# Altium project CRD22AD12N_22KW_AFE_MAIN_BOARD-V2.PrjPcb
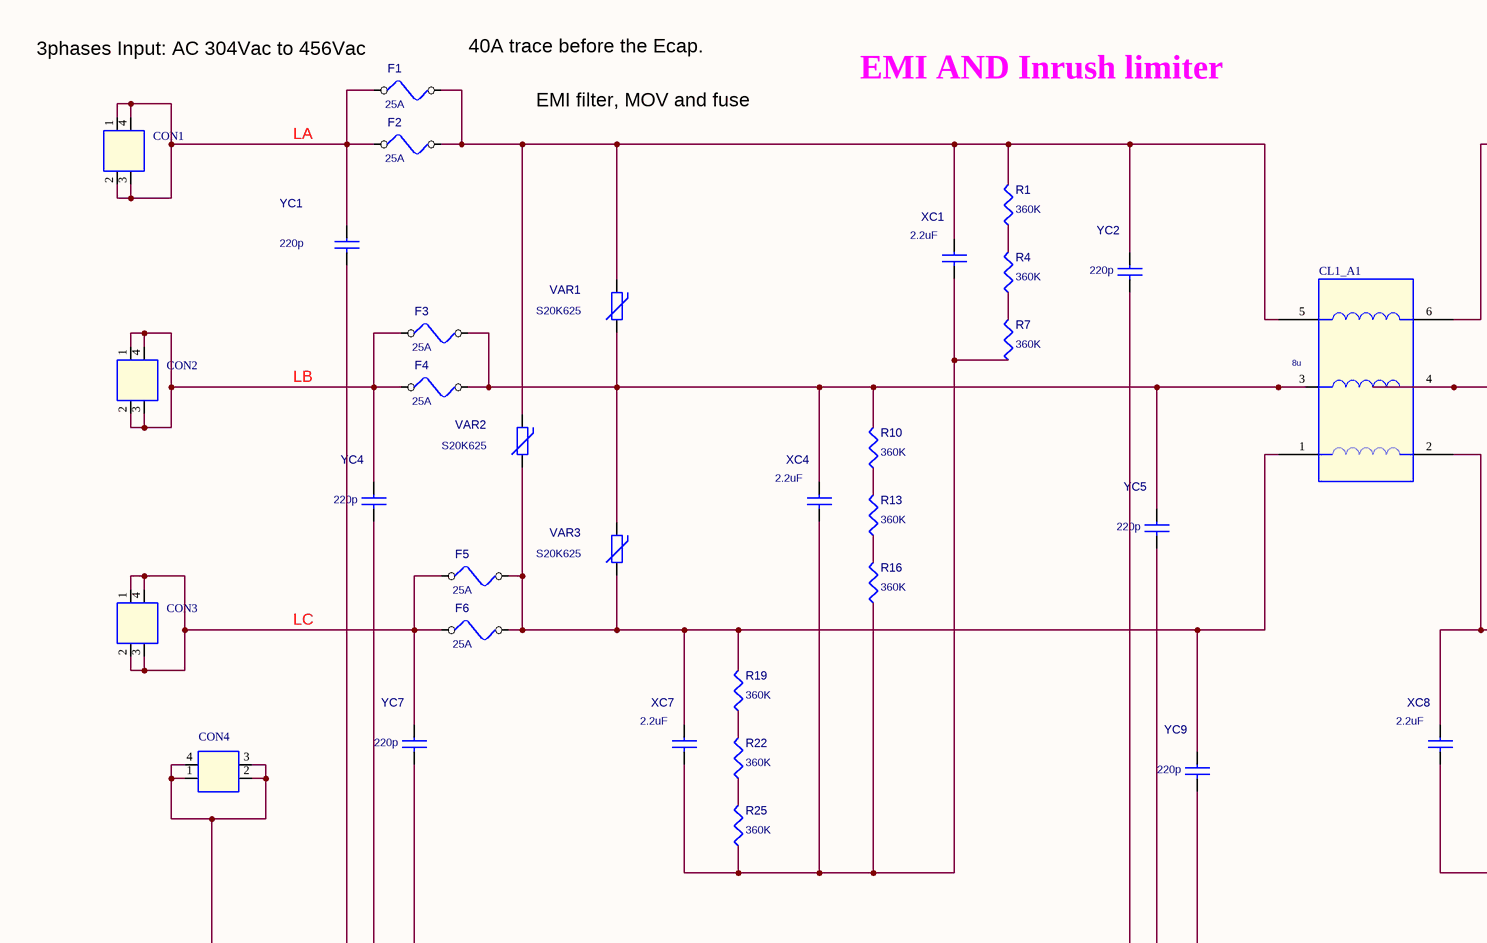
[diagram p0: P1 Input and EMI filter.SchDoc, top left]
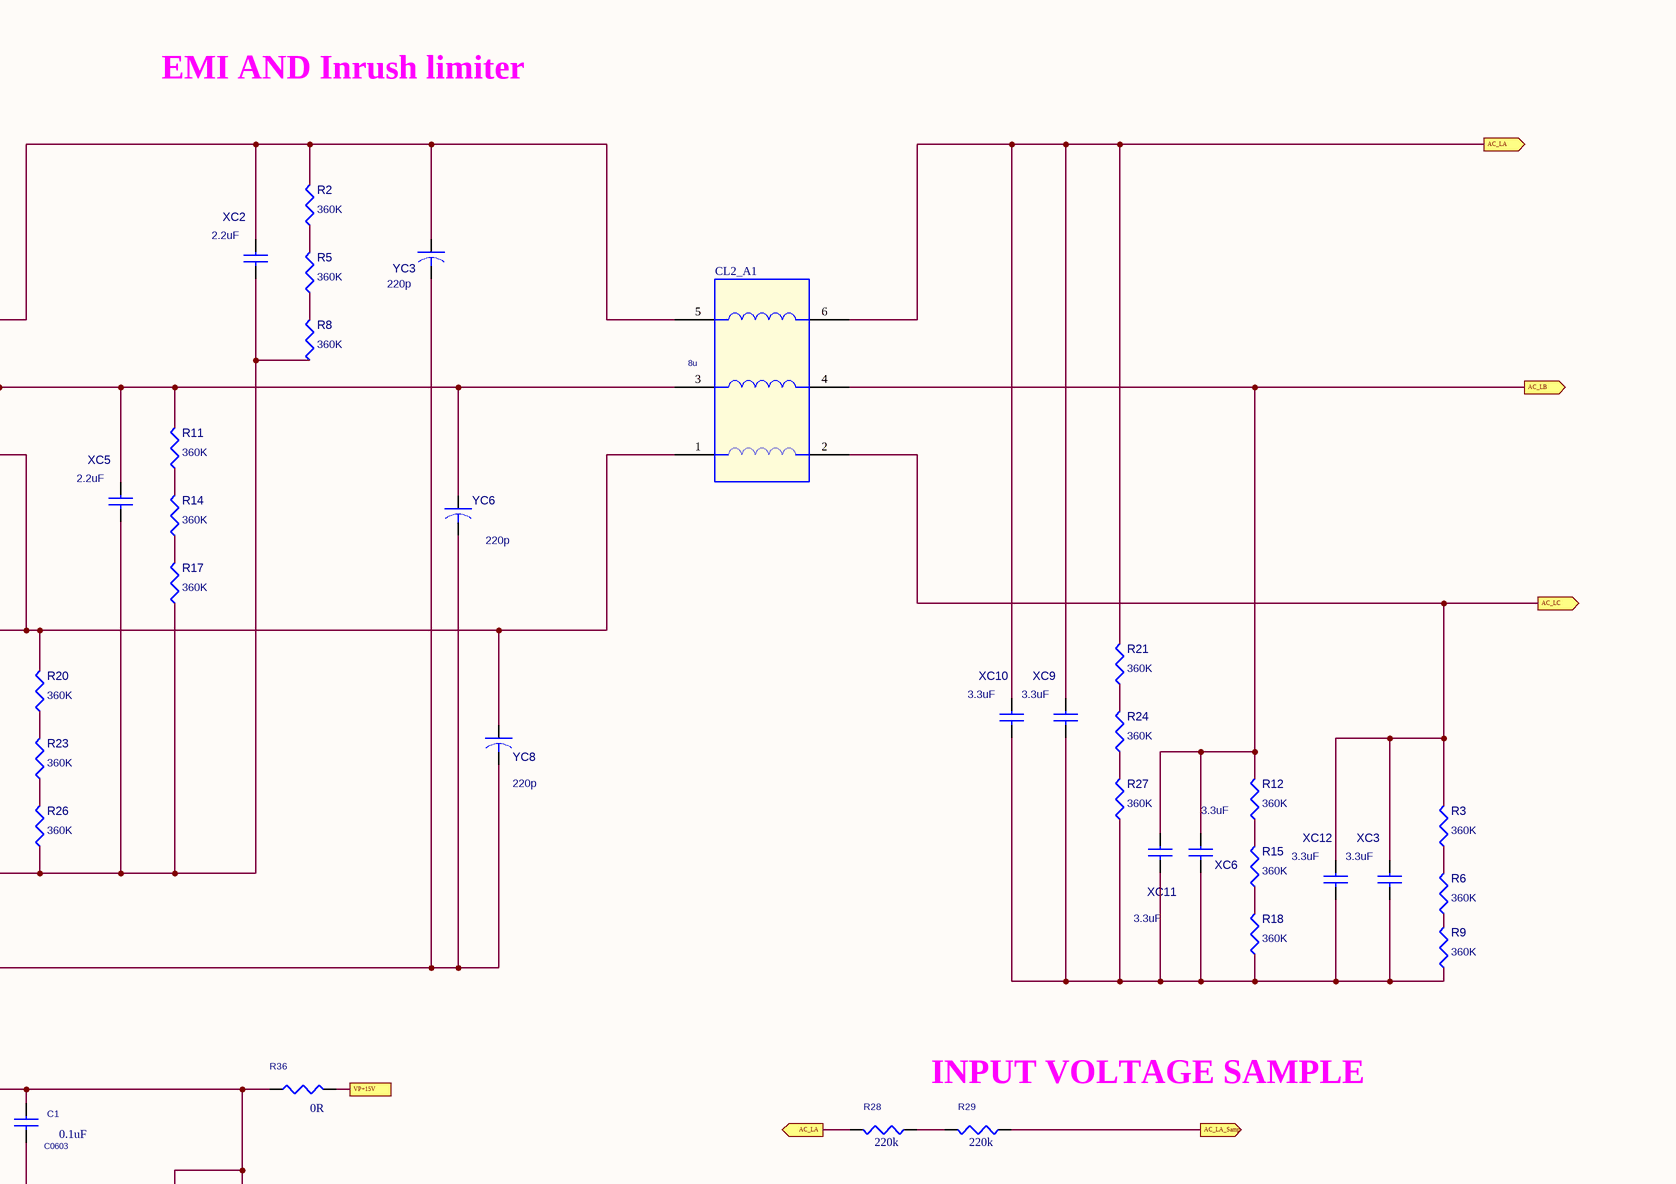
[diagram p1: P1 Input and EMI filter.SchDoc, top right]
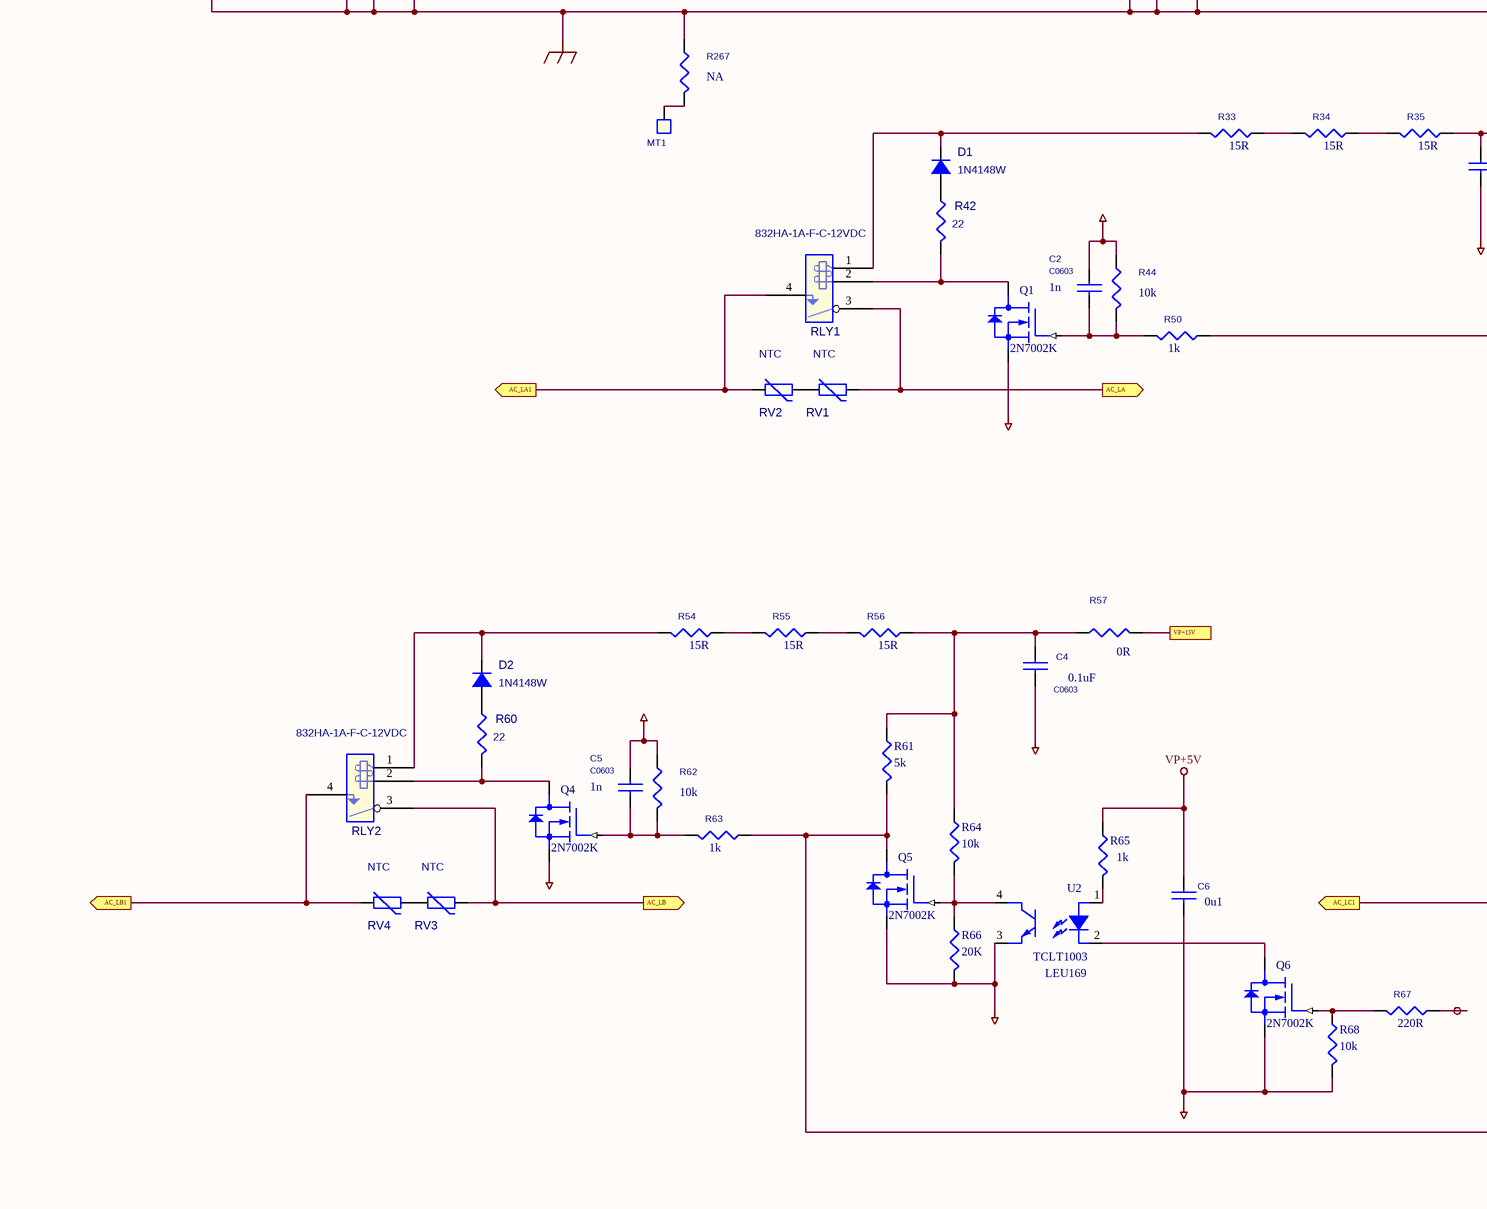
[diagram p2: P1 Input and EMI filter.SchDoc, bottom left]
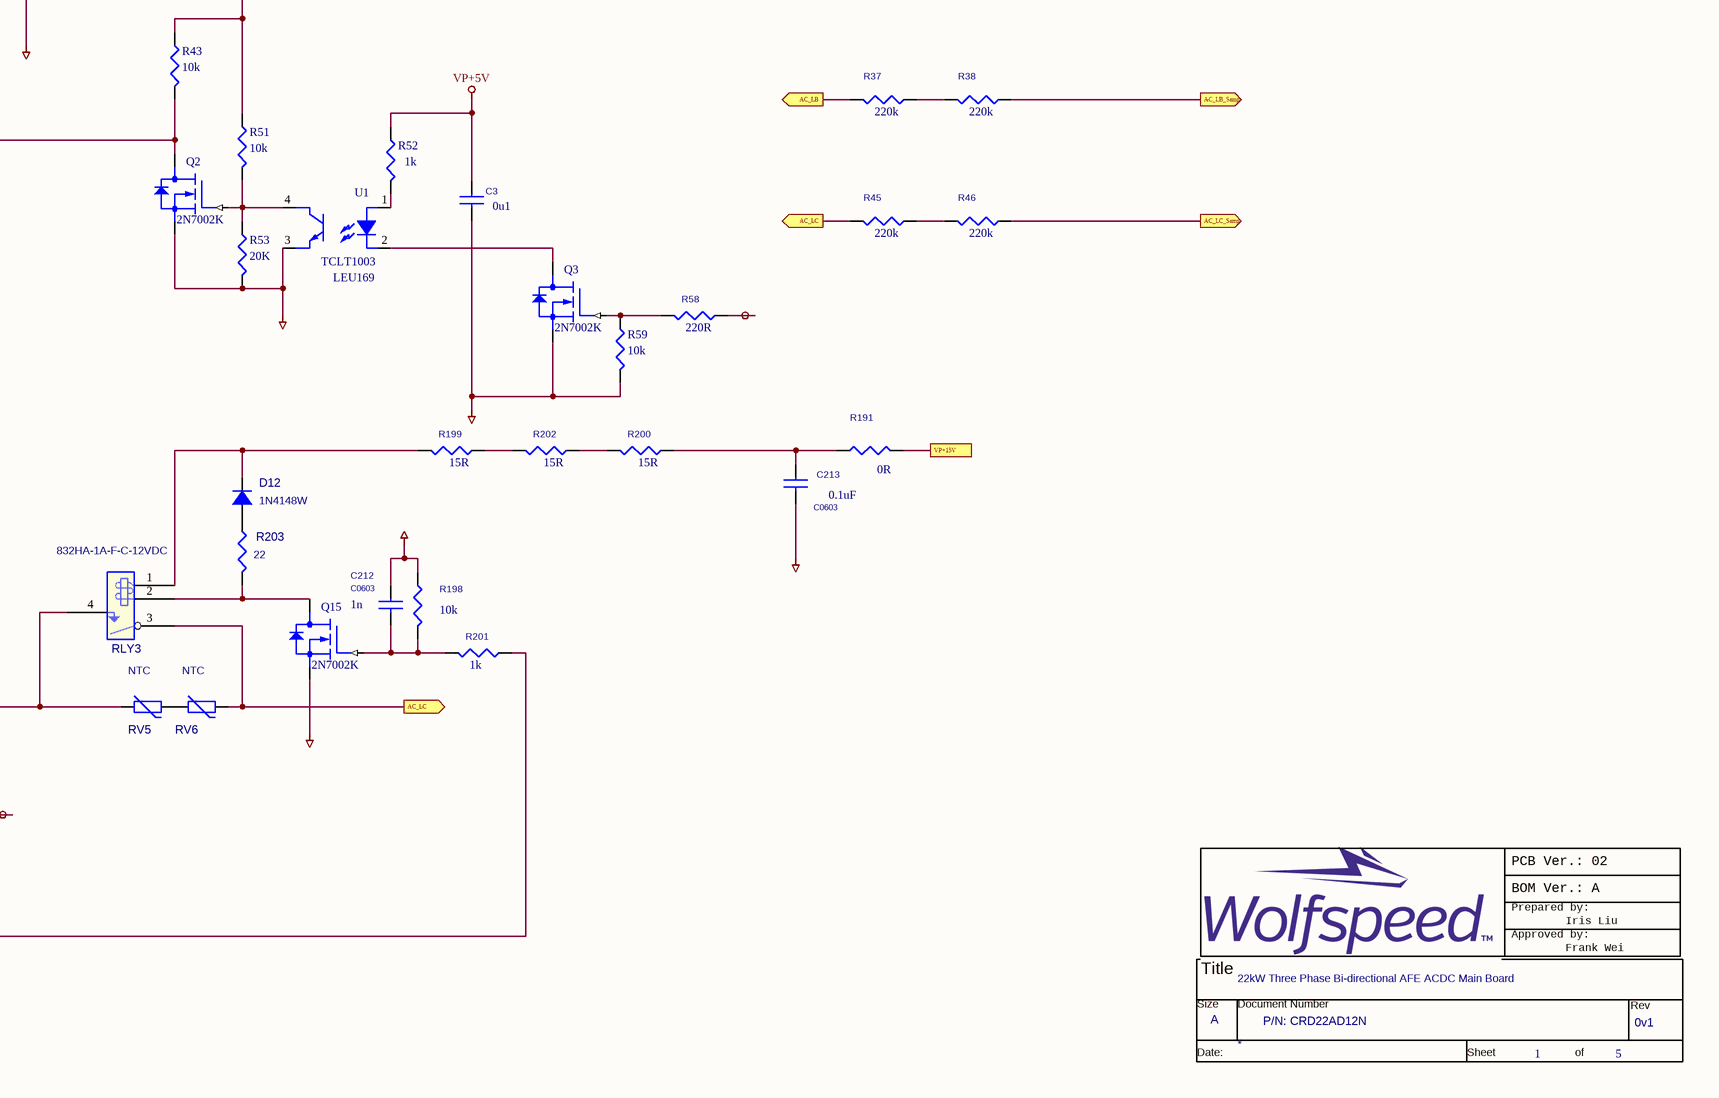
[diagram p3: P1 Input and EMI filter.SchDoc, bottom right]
5 sheets, 580 parts. Net scope: flat (ports and power ports of the same name join across sheets).
Board file: CRD22AD12N_22KW_AFE_MAIN_BOARD-V2.PcbDoc
Sheets:
  P1 Input and EMI filter.SchDoc
  P2 PFC.SchDoc
  P3 Bias POWER SUPPLY.SchDoc
  P4 PFC Gate Driver.SchDoc
  P5 PFC sampling.SchDoc

## Sheet P1 Input and EMI filter.SchDoc
size 594 x 420 mm

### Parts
(Parts that share a designator on the sheet are numbered #1, #2 ... from top to bottom, then left to right.)
*#1  Doc: P/N: CRD22AD12N  RevCode: 0v1  Title: 22kW Three Phase Bi-directional AFE ACDC Main Board  Page Size: A  Page Number: 1  Page Count: 5  (hidden comment: TitleBlock0_cree_power)  (graphical)
C1  0.1uF  [C0603]
C2  1n  [C0603]
C3  0u1  [C0603]
C4  0.1uF  [C0603]
C5  1n  [C0603]
C6  0u1  [C0603]
C212  1n  [C0603]
C213  0.1uF  [C0603]
CL1_A1  8u  [LCM1]
CL2_A1  8u  [LCM1]
CON1  Connecter  [thread4_9p9x5_1110x920]  (value not drawn)
CON2  Connecter  [thread4_9p9x5_1110x920]  (value not drawn)
CON3  Connecter  [thread4_9p9x5_1110x920]  (value not drawn)
CON4  Connecter  [thread4_9p9x5_1110x920]  (value not drawn)
D1  1N4148W  [SOD-123]
D2  1N4148W  [SOD-123]
D12  1N4148W  [SOD-123]
F1  25A  [FULSE]
F2  25A  [FULSE]
F3  25A  [FULSE]
F4  25A  [FULSE]
F5  25A  [FULSE]
F6  25A  [FULSE]
MT1  T1T2  [MTH122]  (value not drawn)
Q1  2N7002K  [SOT-23]
Q2  2N7002K  [SOT-23]
Q3  2N7002K  [SOT-23]
Q4  2N7002K  [SOT-23]
Q5  2N7002K  [SOT-23]
Q6  2N7002K  [SOT-23]
Q15  2N7002K  [SOT-23]
R1  360K  [R1206]
R2  360K  [R1206]
R3  360K  [R1206]
R4  360K  [R1206]
R5  360K  [R1206]
R6  360K  [R1206]
R7  360K  [R1206]
R8  360K  [R1206]
R9  360K  [R1206]
R10  360K  [R1206]
R11  360K  [R1206]
R12  360K  [R1206]
R13  360K  [R1206]
R14  360K  [R1206]
R15  360K  [R1206]
R16  360K  [R1206]
R17  360K  [R1206]
R18  360K  [R1206]
R19  360K  [R1206]
R20  360K  [R1206]
R21  360K  [R1206]
R22  360K  [R1206]
R23  360K  [R1206]
R24  360K  [R1206]
R25  360K  [R1206]
R26  360K  [R1206]
R27  360K  [R1206]
R28  220k  [R1206]
R29  220k  [R1206]
R33  15R  [R1206]
R34  15R  [R1206]
R35  15R  [R1206]
R36  0R  [R0603]
R37  220k  [R1206]
R38  220k  [R1206]
R42  22  [R1206]
R43  10k  [R0603]
R44  10k  [R0603]
R45  220k  [R1206]
R46  220k  [R1206]
R50  1k  [R0603]
R51  10k  [R0603]
R52  1k  [R0603]
R53  20K  [R0603]
R54  15R  [R1206]
R55  15R  [R1206]
R56  15R  [R1206]
R57  0R  [R0603]
R58  220R  [R0603]
R59  10k  [R0603]
R60  22  [R1206]
R61  5k  [R0603]
R62  10k  [R0603]
R63  1k  [R0603]
R64  10k  [R0603]
R65  1k  [R0603]
R66  20K  [R0603]
R67  220R  [R0603]
R68  10k  [R0603]
R191  0R  [R0603]
R198  10k  [R0603]
R199  15R  [R1206]
R200  15R  [R1206]
R201  1k  [R0603]
R202  15R  [R1206]
R203  22  [R1206]
R267  NA  [R1206]
RLY1  832HA-1A-F-C-12VDC  [T9SV1K15-12]
RLY2  832HA-1A-F-C-12VDC  [T9SV1K15-12]
RLY3  832HA-1A-F-C-12VDC  [T9SV1K15-12]
RV1  NTC  [NTC_od20MM]
RV2  NTC  [NTC_od20MM]
RV3  NTC  [NTC_od20MM]
RV4  NTC  [NTC_od20MM]
RV5  NTC  [NTC_od20MM]
RV6  NTC  [NTC_od20MM]
U1  TCLT1003  LLF Part Number: LEU169  [opto-sop-4l]
U2  TCLT1003  LLF Part Number: LEU169  [opto-sop-4l]
VAR1  S20K625  [MOV_OD21P5MM_PI10MM_PINV3P3MM]
VAR2  S20K625  [MOV_OD21P5MM_PI10MM_PINV3P3MM]
VAR3  S20K625  [MOV_OD21P5MM_PI10MM_PINV3P3MM]
XC1  2.2uF  [CAPFILM_26_5X12MM]
XC2  2.2uF  [CAPFILM_26_5X12MM]
XC3  3.3uF  [CAPFILM_26_5X15MM]
XC4  2.2uF  [CAPFILM_26_5X12MM]
XC5  2.2uF  [CAPFILM_26_5X12MM]
XC6  3.3uF  [CAPFILM_26_5X15MM]
XC7  2.2uF  [CAPFILM_26_5X12MM]
XC8  2.2uF  [CAPFILM_26_5X12MM]
XC9  3.3uF  [CAPFILM_26_5X15MM]
XC10  3.3uF  [CAPFILM_26_5X15MM]
XC11  3.3uF  [CAPFILM_26_5X15MM]
XC12  3.3uF  [CAPFILM_26_5X15MM]
YC1  220p  [C1812]
YC2  220p  [C1812]
YC3  220p  [C1812]
YC4  220p  [C1812]
YC5  220p  [C1812]
YC6  220p  [C1812]
YC7  220p  [C1812]
YC8  220p  [C1812]
YC9  220p  [C1812]

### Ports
AC_LA1 (out), AC_LA (out), AC_LA_Samp (out), AC_LB1 (out), AC_LB (out), AC_LB_Samp (out), AC_LC1 (out), AC_LC (out), AC_LC_Samp (out), VP+15V

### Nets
AGND: C3.2 C6.2 Q3.2(SOURCE) Q6.2(SOURCE) R59.1 R68.1
GGND: C1.2 C2.1 C4.2 C5.1 C212.1 C213.2 Q1.2(SOURCE) Q2.2(SOURCE) Q4.2(SOURCE) Q5.2(SOURCE) Q15.2(SOURCE) R44.2 R53.1 R62.2 R66.1 R198.2 U1.3 U2.3
GND_EARTH: CON4.1 CON4.2 CON4.3 CON4.4 R267.1 YC1.2 YC2.2 YC3.2 YC4.2 YC5.2 YC6.2 YC7.2 YC8.2 YC9.2
RLYCTRL1: R58.2
RLYCTRL2: R67.2
VP+5V: C3.1 C6.1 R52.2 R65.2
LA: CON1.1 CON1.2 CON1.3 CON1.4 F1.1 F2.1 YC1.1
LB: CON2.1 CON2.2 CON2.3 CON2.4 F3.1 F4.1 YC4.1
LC: CON3.1 CON3.2 CON3.3 CON3.4 F5.1 F6.1 YC7.1
NetC1_1: C1.1 R35.2 R36.2 R43.2 R51.2
NetC2_2: C2.2 Q1.1(GATE) R44.1 R50.1
NetC4_1: C4.1 R56.2 R57.2 R61.2 R64.2
NetC5_2: C5.2 Q4.1(GATE) R62.1 R63.1
NetC212_2: C212.2 Q15.1(GATE) R198.1 R201.1
NetC213_1: C213.1 R191.2 R200.2
NetCL1_A1_1: CL1_A1.1 F5.2 F6.2 R19.2 VAR2.1 VAR3.1 XC7.1 YC9.1
NetCL1_A1_2: CL1_A1.2 CL2_A1.1 R20.2 XC8.1 YC8.1
NetCL1_A1_3: CL1_A1.3 F3.2 F4.2 R10.2 VAR1.1 VAR3.2 XC4.1 YC5.1
NetCL1_A1_4: CL1_A1.4 CL2_A1.3 R11.2 XC5.1 YC6.1
NetCL1_A1_5: CL1_A1.5 F1.2 F2.2 R1.2 VAR1.2 VAR2.2 XC1.1 YC2.1
NetCL1_A1_6: CL1_A1.6 CL2_A1.5 R2.2 XC2.1 YC3.1
NetCL2_A1_2: CL2_A1.2 R3.2 R45.1 RLY3.3(COMMON) RV6.2 XC3.1 XC12.1 ; port AC_LC
NetCL2_A1_4: CL2_A1.4 R12.2 R37.1 RLY2.3(COMMON) RV3.2 XC6.1 XC11.1 ; port AC_LB
NetCL2_A1_6: CL2_A1.6 R21.2 R28.1 RLY1.3(COMMON) RV1.2 XC9.1 XC10.1 ; port AC_LA
NetD1_1: D1.1(A) R42.1
NetD1_2: D1.2(K) R33.1 RLY1.1(COIL2)
NetD2_1: D2.1(A) R60.1
NetD2_2: D2.2(K) R54.1 RLY2.1(COIL2)
NetD12_1: D12.1(A) R203.1
NetD12_2: D12.2(K) R199.1 RLY3.1(COIL2)
NetJ4_5: R36.1 R57.1 R191.1 ; port VP+15V
NetMT1_1: MT1.1 R267.2
NetQ1_3: Q1.3(DRAIN) R42.2 RLY1.2(COIL1)
NetQ2_1: Q2.1(GATE) R51.1 R53.2 U1.4
NetQ2_3: Q2.3(DRAIN) R43.1 R50.2
NetQ3_1: Q3.1(GATE) R58.1 R59.2
NetQ3_3: Q3.3(DRAIN) U1.2
NetQ4_3: Q4.3(DRAIN) R60.2 RLY2.2(COIL1)
NetQ5_1: Q5.1(GATE) R64.1 R66.2 U2.4
NetQ5_3: Q5.3(DRAIN) R61.1 R63.2 R201.2
NetQ6_1: Q6.1(GATE) R67.1 R68.2
NetQ6_3: Q6.3(DRAIN) U2.2
NetQ15_3: Q15.3(DRAIN) R203.2 RLY3.2(COIL1)
NetR1_1: R1.1 R4.2
NetR2_1: R2.1 R5.2
NetR3_1: R3.1 R6.2
NetR4_1: R4.1 R7.2
NetR5_1: R5.1 R8.2
NetR6_1: R6.1 R9.2
NetR7_1: R7.1 R16.1 R25.1 XC1.2 XC4.2 XC7.2
NetR8_1: R8.1 R17.1 R26.1 XC2.2 XC5.2 XC8.2
NetR9_1: R9.1 R18.1 R27.1 XC3.2 XC6.2 XC9.2 XC10.2 XC11.2 XC12.2
NetR10_1: R10.1 R13.2
NetR11_1: R11.1 R14.2
NetR12_1: R12.1 R15.2
NetR13_1: R13.1 R16.2
NetR14_1: R14.1 R17.2
NetR15_1: R15.1 R18.2
NetR19_1: R19.1 R22.2
NetR20_1: R20.1 R23.2
NetR21_1: R21.1 R24.2
NetR22_1: R22.1 R25.2
NetR23_1: R23.1 R26.2
NetR24_1: R24.1 R27.2
NetR28_2: R28.2 R29.1
NetR29_2: R29.2 ; port AC_LA_Samp
NetR33_2: R33.2 R34.1
NetR34_2: R34.2 R35.1
NetR37_2: R37.2 R38.1
NetR38_2: R38.2 ; port AC_LB_Samp
NetR45_2: R45.2 R46.1
NetR46_2: R46.2 ; port AC_LC_Samp
NetR52_1: R52.1 U1.1
NetR54_2: R54.2 R55.1
NetR55_2: R55.2 R56.1
NetR65_1: R65.1 U2.1
NetR199_2: R199.2 R202.1
NetR200_1: R200.1 R202.2
NetRLY1_4: RLY1.4(NO) RV2.1 ; port AC_LA1
NetRLY2_4: RLY2.4(NO) RV4.1 ; port AC_LB1
NetRLY3_4: RLY3.4(NO) RV5.1 ; port AC_LC1
NetRV1_1: RV1.1 RV2.2
NetRV3_1: RV3.1 RV4.2
NetRV5_2: RV5.2 RV6.1

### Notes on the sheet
- (near F1) 3phases Input: AC 304Vac to 456Vac
- (near F1) 40A trace before the Ecap.
- EMI AND Inrush limiter
- EMI filter, MOV and fuse
- INPUT VOLTAGE SAMPLE
- PCB Ver.: 02
- BOM Ver.: A
- Prepared by:
- Approved by:
- .
- Frank Wei
- Iris Liu

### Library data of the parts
C1-C6 C212 C213 XC1-XC12 YC1 YC2 YC4 YC5 YC7 YC9 = CAP NP
CL1_A1 CL2_A1 = 126LNS_5
D1 D2 D12 = DIODE_0
F1-F6 = FUSE_0
MT1 = CON1_2
Q1-Q6 Q15 = 2N7002/SOT
R1-R27 = R_2
R28 R29 R33-R38 R43-R46 R50-R59 R61-R68 R191 R198-R202 R267 = RESISTOR
R42 R60 R203 = RESISTOR_Dup1
RLY1-RLY3 = RELAY SPST_1
RV1-RV6 VAR1-VAR3 = VARISTOR
U1 U2 = LEU169_TCLT1003_SOP-4L
YC3 YC6 YC8 = CAP

## Sheet P2 PFC.SchDoc
size 594 x 420 mm
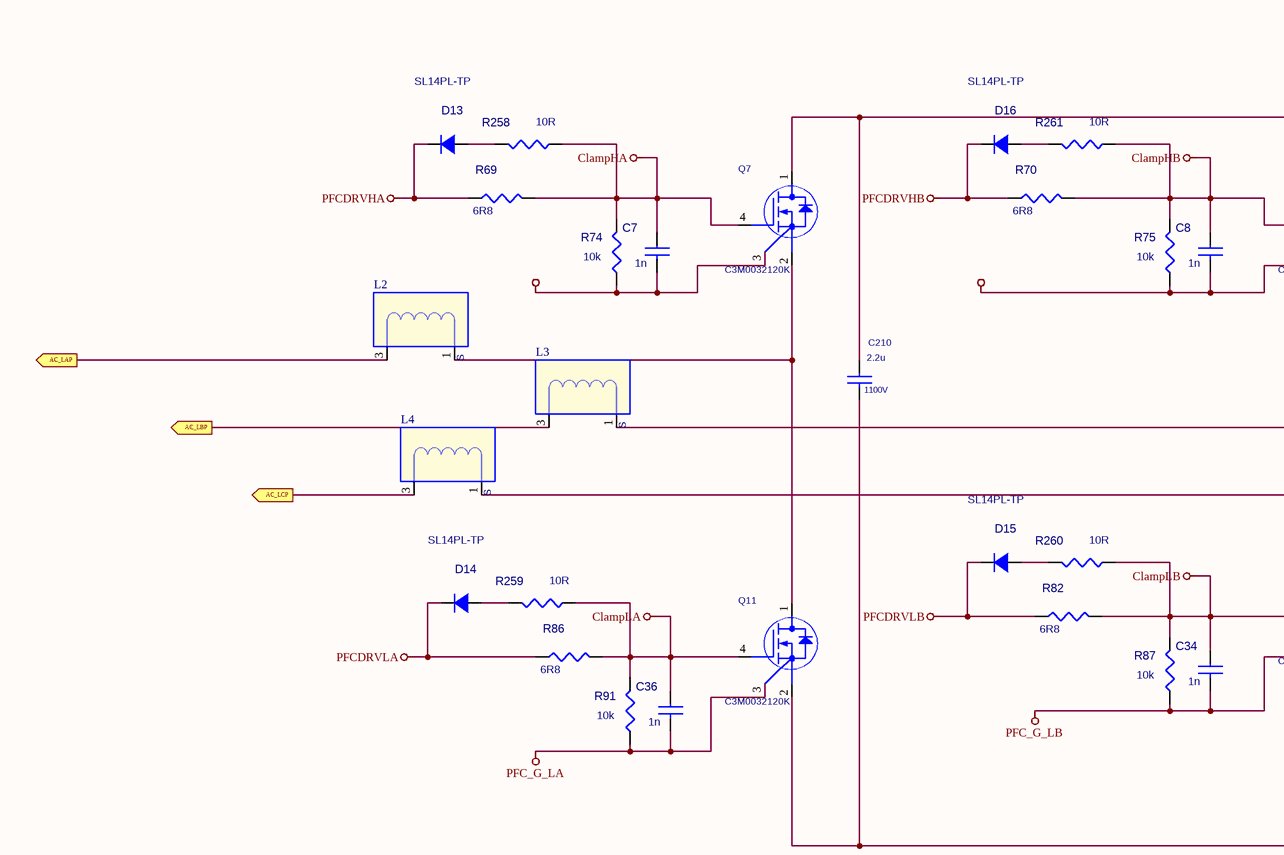
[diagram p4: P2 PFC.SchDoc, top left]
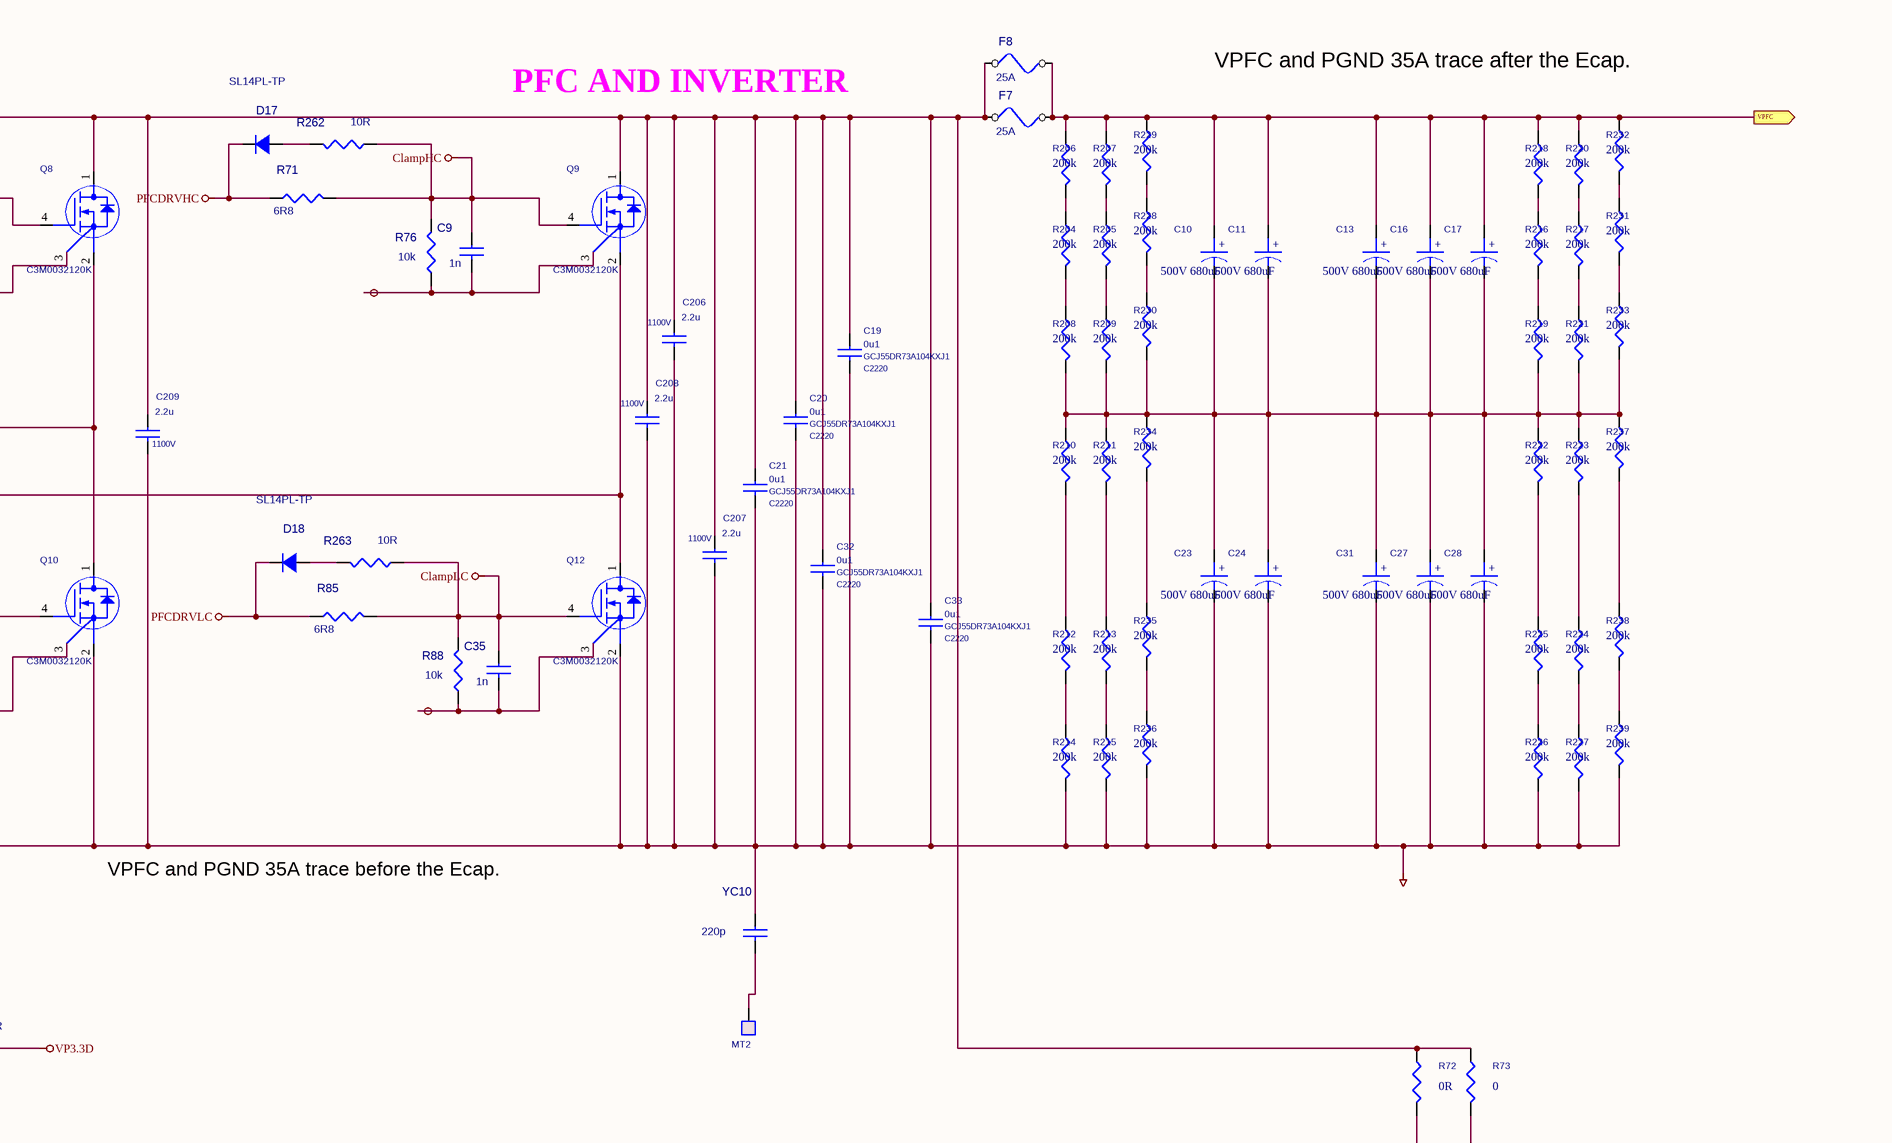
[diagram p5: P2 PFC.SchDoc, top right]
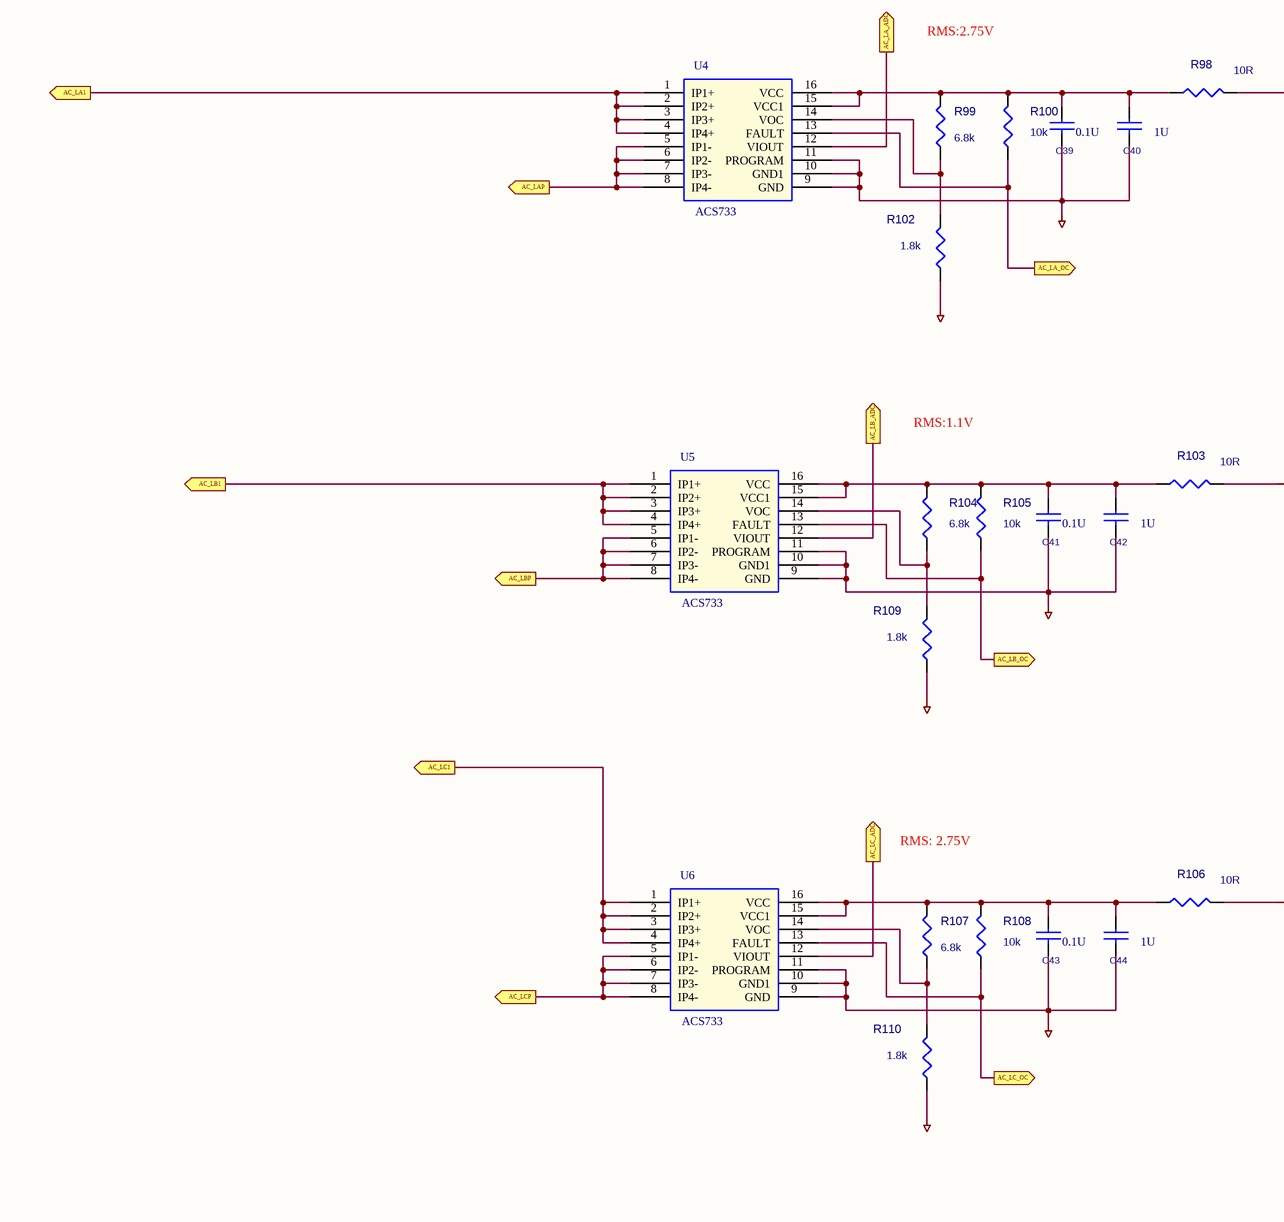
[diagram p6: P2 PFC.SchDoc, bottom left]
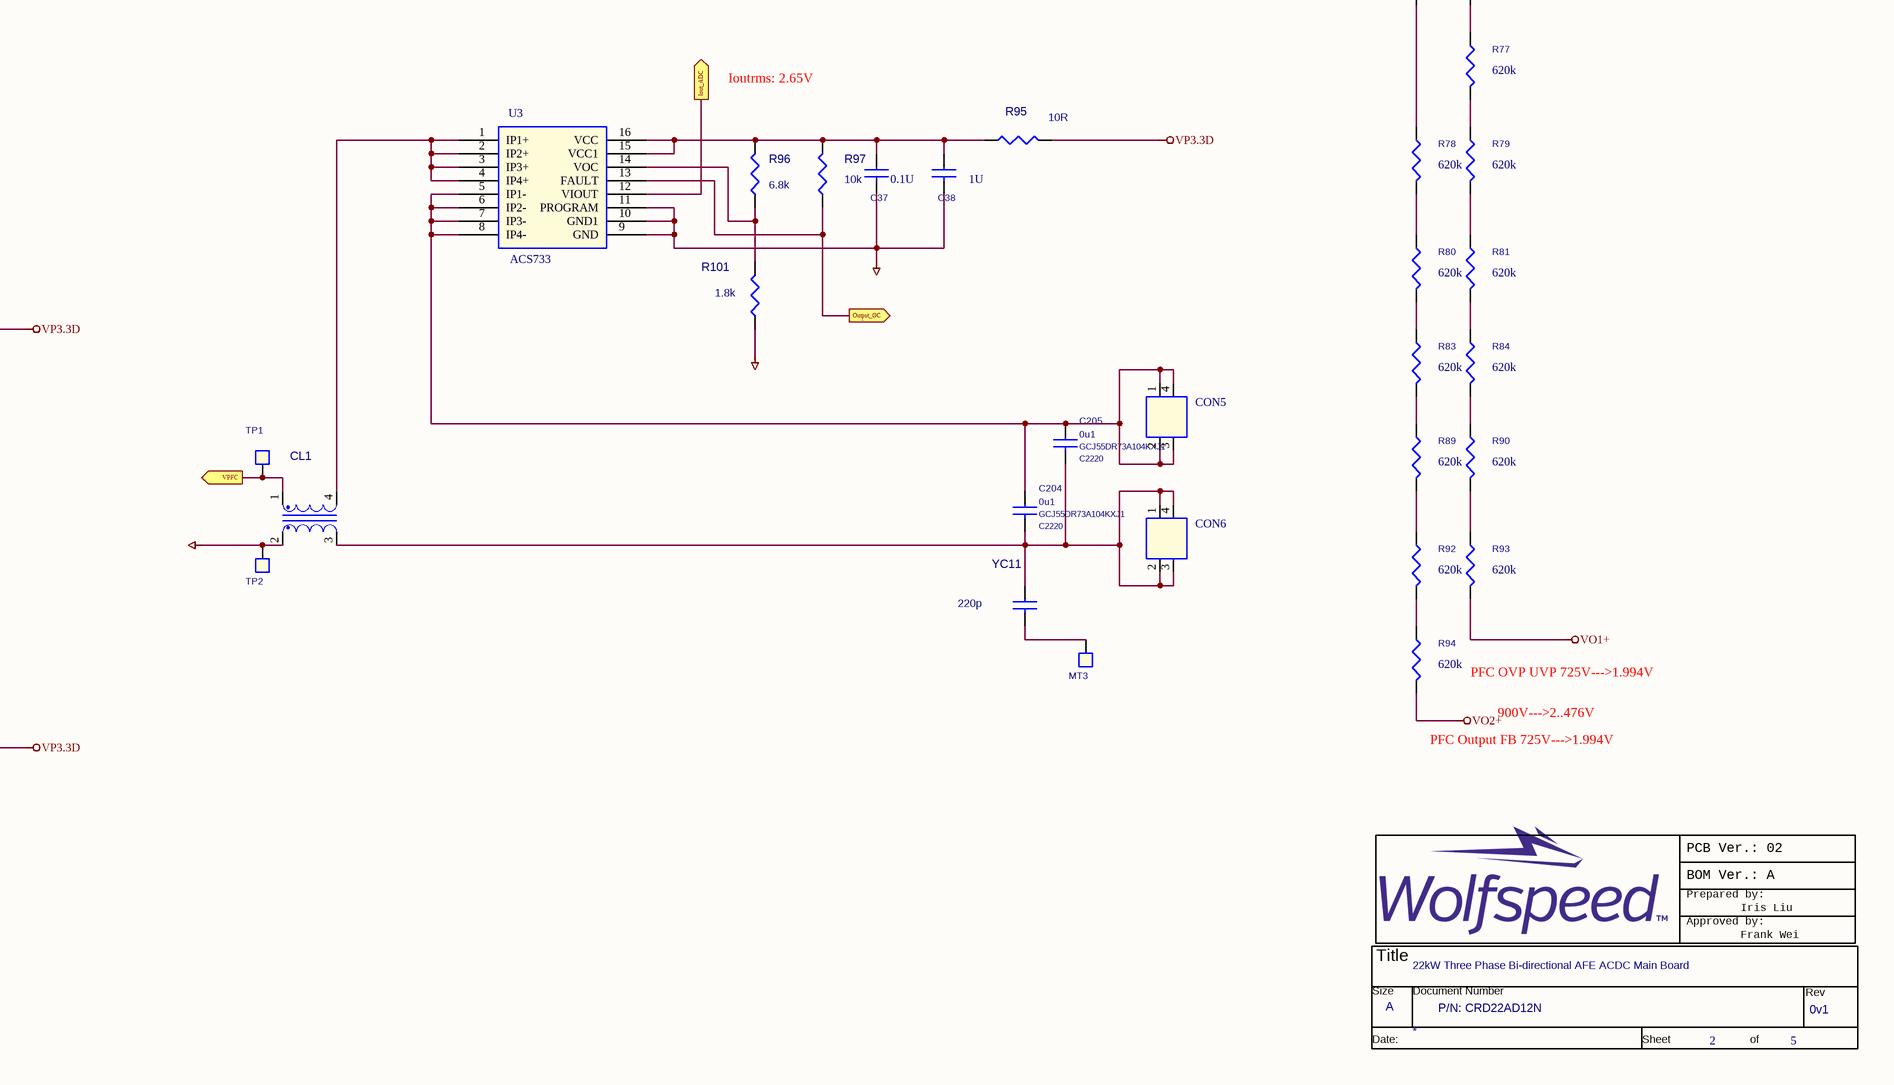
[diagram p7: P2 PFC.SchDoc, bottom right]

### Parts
(Parts that share a designator on the sheet are numbered #1, #2 ... from top to bottom, then left to right.)
*#2  Doc: P/N: CRD22AD12N  RevCode: 0v1  Title: 22kW Three Phase Bi-directional AFE ACDC Main Board  Page Size: A  Page Number: 2  Page Count: 5  (hidden comment: TitleBlock0_cree_power)  (graphical)
C7  1n  [C0603]
C8  1n  [C0603]
C9  1n  [C0603]
C10  500V 680uF  [ecap_d35p7_25]
C11  500V 680uF  [ecap_d35p7_25]
C13  500V 680uF  [ecap_d35p7_25]
C16  500V 680uF  [ecap_d35p7_25]
C17  500V 680uF  [ecap_d35p7_25]
C19  0u1  value1: GCJ55DR73A104KXJ1  [C2220]
C20  0u1  value1: GCJ55DR73A104KXJ1  [C2220]
C21  0u1  value1: GCJ55DR73A104KXJ1  [C2220]
C23  500V 680uF  [ecap_d35p7_25]
C24  500V 680uF  [ecap_d35p7_25]
C27  500V 680uF  [ecap_d35p7_25]
C28  500V 680uF  [ecap_d35p7_25]
C31  500V 680uF  [ecap_d35p7_25]
C32  0u1  value1: GCJ55DR73A104KXJ1  [C2220]
C33  0u1  value1: GCJ55DR73A104KXJ1  [C2220]
C34  1n  [C0603]
C35  1n  [C0603]
C36  1n  [C0603]
C37  0.1U  [C0603]
C38  1U  [C0603]
C39  0.1U  [C0603]
C40  1U  [C0603]
C41  0.1U  [C0603]
C42  1U  [C0603]
C43  0.1U  [C0603]
C44  1U  [C0603]
C204  0u1  value1: GCJ55DR73A104KXJ1  [C2220]
C205  0u1  value1: GCJ55DR73A104KXJ1  [C2220]
C206  2.2u  value1: 1100V  [capfilm_31_5x12_5mm]
C207  2.2u  value1: 1100V  [capfilm_31_5x12_5mm]
C208  2.2u  value1: 1100V  [capfilm_31_5x12_5mm]
C209  2.2u  value1: 1100V  [capfilm_31_5x12_5mm]
C210  2.2u  value1: 1100V  [capfilm_31_5x12_5mm]
CL1  6Ts  [CM_4P]  (value not drawn)
CON5  Connecter  [thread4_9p9x5_1110x920]  (value not drawn)
CON6  Connecter  [thread4_9p9x5_1110x920]  (value not drawn)
D13  SL14PL-TP  [SOD-123]
D14  SL14PL-TP  [SOD-123]
D15  SL14PL-TP  [SOD-123]
D16  SL14PL-TP  [SOD-123]
D17  SL14PL-TP  [SOD-123]
D18  SL14PL-TP  [SOD-123]
F7  25A  [FULSE]
F8  25A  [FULSE]
L2  8u  [L71mm]  (value not drawn)
L3  8u  [L71mm]  (value not drawn)
L4  8u  [L71mm]  (value not drawn)
MT2  T1T2  [MTH122]  (value not drawn)
MT3  T1T2  [MTH122]  (value not drawn)
Q7  C3M0032120K  [to-247-4l]
Q8  C3M0032120K  [to-247-4l]
Q9  C3M0032120K  [to-247-4l]
Q10  C3M0032120K  [to-247-4l]
Q11  C3M0032120K  [to-247-4l]
Q12  C3M0032120K  [to-247-4l]
R69  6R8  [R1206]
R70  6R8  [R1206]
R71  6R8  [R1206]
R72  0R  [R1206]
R73  0  [R1206]
R74  10k  [R0603]
R75  10k  [R0603]
R76  10k  [R0603]
R77  620k  [R1206]
R78  620k  [R1206]
R79  620k  [R1206]
R80  620k  [R1206]
R81  620k  [R1206]
R82  6R8  [R1206]
R83  620k  [R1206]
R84  620k  [R1206]
R85  6R8  [R1206]
R86  6R8  [R1206]
R87  10k  [R0603]
R88  10k  [R0603]
R89  620k  [R1206]
R90  620k  [R1206]
R91  10k  [R0603]
R92  620k  [R1206]
R93  620k  [R1206]
R94  620k  [R1206]
R95  10R  [R0603]
R96  6.8k  [R0603]
R97  10k  [R0603]
R98  10R  [R0603]
R99  6.8k  [R0603]
R100  10k  [R0603]
R101  1.8k  [R0603]
R102  1.8k  [R0603]
R103  10R  [R0603]
R104  6.8k  [R0603]
R105  10k  [R0603]
R106  10R  [R0603]
R107  6.8k  [R0603]
R108  10k  [R0603]
R109  1.8k  [R0603]
R110  1.8k  [R0603]
R204  200k  [R1206]
R205  200k  [R1206]
R206  200k  [R1206]
R207  200k  [R1206]
R208  200k  [R1206]
R209  200k  [R1206]
R210  200k  [R1206]
R211  200k  [R1206]
R212  200k  [R1206]
R213  200k  [R1206]
R214  200k  [R1206]
R215  200k  [R1206]
R216  200k  [R1206]
R217  200k  [R1206]
R218  200k  [R1206]
R219  200k  [R1206]
R220  200k  [R1206]
R221  200k  [R1206]
R222  200k  [R1206]
R223  200k  [R1206]
R224  200k  [R1206]
R225  200k  [R1206]
R226  200k  [R1206]
R227  200k  [R1206]
R228  200k  [R1206]
R229  200k  [R1206]
R230  200k  [R1206]
R231  200k  [R1206]
R232  200k  [R1206]
R233  200k  [R1206]
R234  200k  [R1206]
R235  200k  [R1206]
R236  200k  [R1206]
R237  200k  [R1206]
R238  200k  [R1206]
R239  200k  [R1206]
R258  10R  [R1206]
R259  10R  [R1206]
R260  10R  [R1206]
R261  10R  [R1206]
R262  10R  [R1206]
R263  10R  [R1206]
TP1  T1T2  [TH47_CR98]  (value not drawn)
TP2  T1T2  [TH47_CR98]  (value not drawn)
U3  ACS733  [SOICW-16]
U4  ACS733  [SOICW-16]
U5  ACS733  [SOICW-16]
U6  ACS733  [SOICW-16]
YC10  220p  [C1812]
YC11  220p  [C1812]

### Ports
AC_LA1 (out), AC_LA_ADC (out), AC_LA_OC (out), AC_LAP (out), AC_LB1 (out), AC_LB_ADC (out), AC_LB_OC (out), AC_LBP (out), AC_LC1 (out), AC_LC_ADC (out), AC_LC_OC (out), AC_LCP (out), Iout_ADC (out), Output_OC (out), VPFC (out)

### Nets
AGND: C37.2 C38.2 C39.2 C40.2 C41.2 C42.2 C43.2 C44.2 R101.2 R102.2 R109.2 R110.2 U3.9(GND) U3.10(GND1) U3.11(PROGRAM) U4.9(GND) U4.10(GND1) U4.11(PROGRAM) U5.9(GND) U5.10(GND1) U5.11(PROGRAM) U6.9(GND) U6.10(GND1) U6.11(PROGRAM)
ClampHA: C7.1 Q7.4(G) R69.2 R74.2 R258.1
ClampHB: C8.1 Q8.4(G) R70.2 R75.2 R261.1
ClampHC: C9.1 Q9.4(G) R71.2 R76.2 R262.1
ClampLA: C36.1 Q11.4(G) R86.2 R91.2 R259.1
ClampLB: C34.1 Q10.4(G) R82.2 R87.2 R260.1
ClampLC: C35.1 Q12.4(G) R85.2 R88.2 R263.1
PFC_G_HA: C7.2 Q7.3(GS) R74.1
PFC_G_HB: C8.2 Q8.3(GS) R75.1
PFC_G_HC: C9.2 Q9.3(GS) R76.1
PFC_G_LA: C36.2 Q11.3(GS) R91.1
PFC_G_LB: C34.2 Q10.3(GS) R87.1
PFC_G_LC: C35.2 Q12.3(GS) R88.1
PFCDRVHA: D13.2(K) R69.1
PFCDRVHB: D16.2(K) R70.1
PFCDRVHC: D17.2(K) R71.1
PFCDRVLA: D14.2(K) R86.1
PFCDRVLB: D15.2(K) R82.1
PFCDRVLC: D18.2(K) R85.1
PGND: C19.2 C20.2 C21.2 C23.2 C24.2 C27.2 C28.2 C31.2 C32.2 C33.2 C206.2 C207.2 C208.2 C209.2 C210.2 CL1.2(P21) Q10.2(S) Q11.2(S) Q12.2(S) R214.1 R215.1 R226.1 R227.1 R236.1 R239.1 TP2.1 YC10.1
VO1+: R93.1
VO2+: R94.1
VP3.3D: R95.1 R98.1 R103.1 R106.1
NetC10_1: C10.1 C11.1 C13.1 C16.1 C17.1 CL1.1(P11) F7.2 F8.2 R206.2 R207.2 R218.2 R220.2 R229.2 R232.2 TP1.1 ; port VPFC
NetC10_2: C10.2 C11.2 C13.2 C16.2 C17.2 C23.1 C24.1 C27.1 C28.1 C31.1 R208.1 R209.1 R210.2 R211.2 R219.1 R221.1 R222.2 R223.2 R230.1 R233.1 R234.2 R237.2
NetC19_1: C19.1 C20.1 C21.1 C32.1 C33.1 C206.1 C207.1 C208.1 C209.1 C210.1 F7.1 F8.1 Q7.1(D) Q8.1(D) Q9.1(D) R72.2 R73.2
NetC37_1: C37.1 C38.1 R95.2 R96.1 R97.1 U3.15(VCC1) U3.16(VCC)
NetC39_1: C39.1 C40.1 R98.2 R99.1 R100.1 U4.15(VCC1) U4.16(VCC)
NetC41_1: C41.1 C42.1 R103.2 R104.1 R105.1 U5.15(VCC1) U5.16(VCC)
NetC43_1: C43.1 C44.1 R106.2 R107.1 R108.1 U6.15(VCC1) U6.16(VCC)
NetC204_1: C204.1 C205.1 CON5.1 CON5.2 CON5.3 CON5.4 U3.5(IP1-) U3.6(IP2-) U3.7(IP3-) U3.8(IP4-)
NetC204_2: C204.2 C205.2 CL1.3(P22) CON6.1 CON6.2 CON6.3 CON6.4 YC11.1
NetCL1_4: CL1.4(P12) U3.1(IP1+) U3.2(IP2+) U3.3(IP3+) U3.4(IP4+)
NetD13_1: D13.1(A) R258.2
NetD14_1: D14.1(A) R259.2
NetD15_1: D15.1(A) R260.2
NetD16_1: D16.1(A) R261.2
NetD17_1: D17.1(A) R262.2
NetD18_1: D18.1(A) R263.2
NetJ1_8: R100.2 U4.13(FAULT) ; port AC_LA_OC
NetJ1_10: R105.2 U5.13(FAULT) ; port AC_LB_OC
NetJ1_12: R108.2 U6.13(FAULT) ; port AC_LC_OC
NetJ1_14: U3.12(VIOUT) ; port Iout_ADC
NetJ1_15: U4.12(VIOUT) ; port AC_LA_ADC
NetJ1_16: R97.2 U3.13(FAULT) ; port Output_OC
NetJ1_17: U5.12(VIOUT) ; port AC_LB_ADC
NetJ1_19: U6.12(VIOUT) ; port AC_LC_ADC
NetL2_1: L2.1 Q7.2(S) Q11.1(D)
NetL2_3: L2.3 U4.5(IP1-) U4.6(IP2-) U4.7(IP3-) U4.8(IP4-) ; port AC_LAP
NetL3_1: L3.1 Q8.2(S) Q10.1(D)
NetL3_3: L3.3 U5.5(IP1-) U5.6(IP2-) U5.7(IP3-) U5.8(IP4-) ; port AC_LBP
NetL4_1: L4.1 Q9.2(S) Q12.1(D)
NetL4_3: L4.3 U6.5(IP1-) U6.6(IP2-) U6.7(IP3-) U6.8(IP4-) ; port AC_LCP
NetMT2_1: MT2.1 YC10.2
NetMT3_1: MT3.1 YC11.2
NetR72_1: R72.1 R78.2
NetR73_1: R73.1 R77.2
NetR77_1: R77.1 R79.2
NetR78_1: R78.1 R80.2
NetR79_1: R79.1 R81.2
NetR80_1: R80.1 R83.2
NetR81_1: R81.1 R84.2
NetR83_1: R83.1 R89.2
NetR84_1: R84.1 R90.2
NetR89_1: R89.1 R92.2
NetR90_1: R90.1 R93.2
NetR92_1: R92.1 R94.2
NetR96_2: R96.2 R101.1 U3.14(VOC)
NetR99_2: R99.2 R102.1 U4.14(VOC)
NetR104_2: R104.2 R109.1 U5.14(VOC)
NetR107_2: R107.2 R110.1 U6.14(VOC)
NetR204_1: R204.1 R208.2
NetR204_2: R204.2 R206.1
NetR205_1: R205.1 R209.2
NetR205_2: R205.2 R207.1
NetR210_1: R210.1 R212.2
NetR211_1: R211.1 R213.2
NetR212_1: R212.1 R214.2
NetR213_1: R213.1 R215.2
NetR216_1: R216.1 R219.2
NetR216_2: R216.2 R218.1
NetR217_1: R217.1 R221.2
NetR217_2: R217.2 R220.1
NetR222_1: R222.1 R225.2
NetR223_1: R223.1 R224.2
NetR224_1: R224.1 R227.2
NetR225_1: R225.1 R226.2
NetR228_1: R228.1 R230.2
NetR228_2: R228.2 R229.1
NetR231_1: R231.1 R233.2
NetR231_2: R231.2 R232.1
NetR234_1: R234.1 R235.2
NetR235_1: R235.1 R236.2
NetR237_1: R237.1 R238.2
NetR238_1: R238.1 R239.2
NetRLY1_4: U4.1(IP1+) U4.2(IP2+) U4.3(IP3+) U4.4(IP4+) ; port AC_LA1
NetRLY2_4: U5.1(IP1+) U5.2(IP2+) U5.3(IP3+) U5.4(IP4+) ; port AC_LB1
NetRLY3_4: U6.1(IP1+) U6.2(IP2+) U6.3(IP3+) U6.4(IP4+) ; port AC_LC1

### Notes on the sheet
- PFC AND INVERTER
- VPFC and PGND 35A trace after the Ecap.
- VPFC and PGND 35A trace before the Ecap.
- RMS:2.75V
- Ioutrms: 2.65V
- RMS:1.1V
- PFC OVP UVP 725V--->1.994V
- RMS: 2.75V
- PFC Output FB 725V--->1.994V
- 900V--->2..476V
- PCB Ver.: 02
- BOM Ver.: A
- Prepared by:
- Approved by:
- .
- Frank Wei
- Iris Liu

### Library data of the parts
*#2 = TitleBlock0_cree_power: Schematic Page Count: 4; Schematic Page Number: 1
C7-C9 C19-C21 C32-C36 C204-C210 = CAP NP_Dup1
C10 C11 C13 C16 C17 C23 C24 C27 C28 C31 = CAP POL
C37-C44 YC10 YC11 = CAP NP
CL1 = TRNSFMR 67125450_0
D13-D18 = DIODE_0
F7 F8 = FUSE_0
L2-L4 = 126LNS_1
MT2 MT3 TP1 TP2 = CON1_2
Q7-Q12 = C3M0065090J_4
R69-R71 R74-R76 R82 R85-R88 R91 R95-R110 R258-R263 = R
R72 R73 R77-R81 R83 R84 R89 R90 R92-R94 R204-R239 = RESISTOR
U3-U6 = MCR1101_0

## Sheet P3 Bias POWER SUPPLY.SchDoc
size 840 x 594 mm
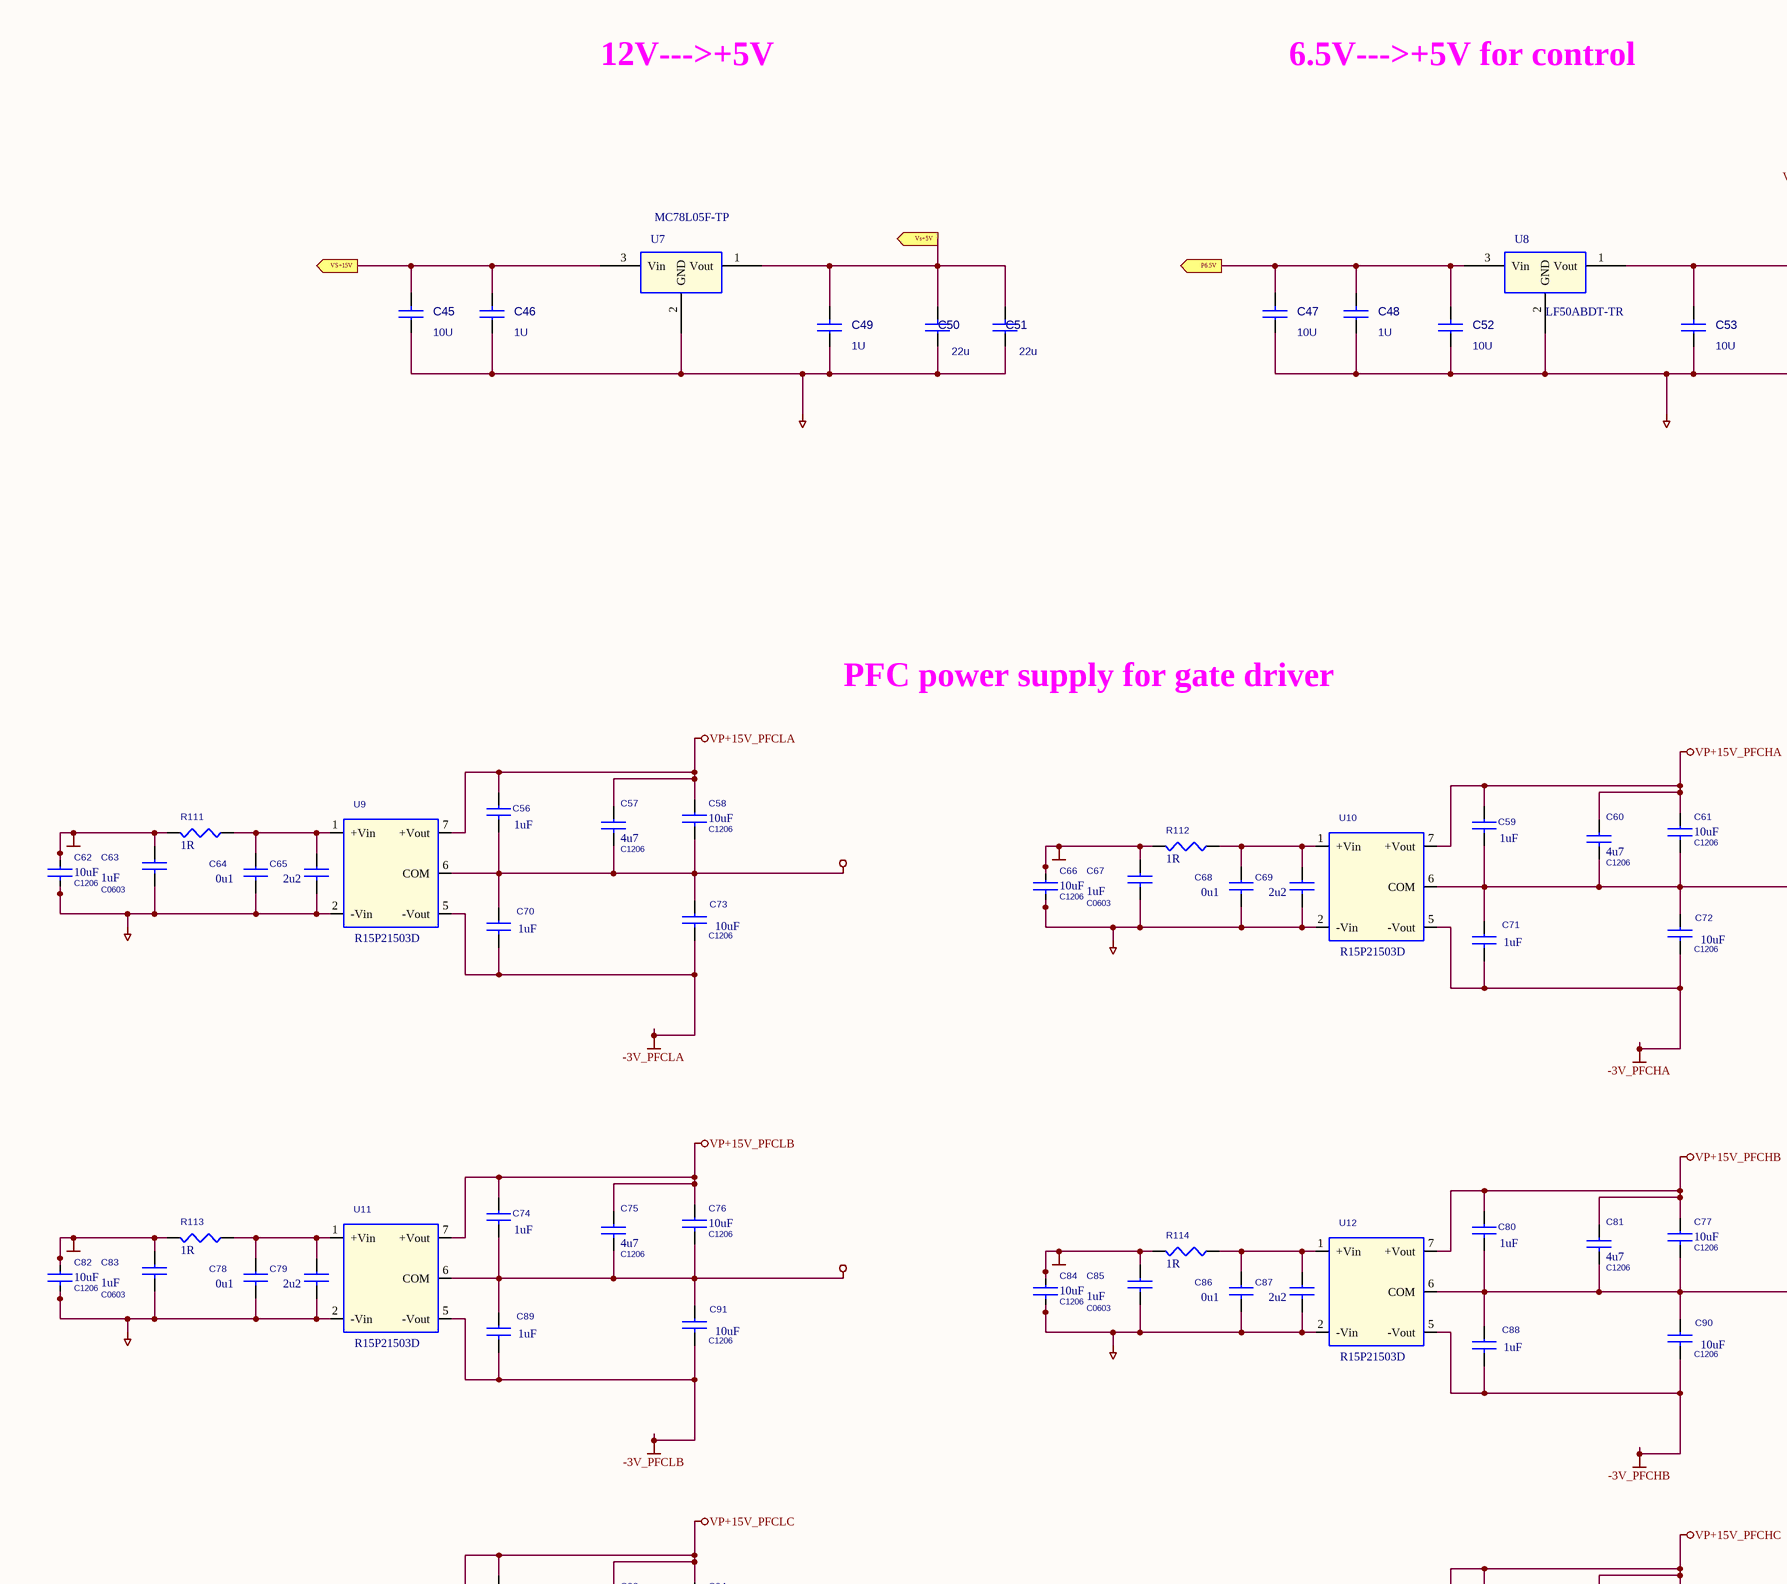
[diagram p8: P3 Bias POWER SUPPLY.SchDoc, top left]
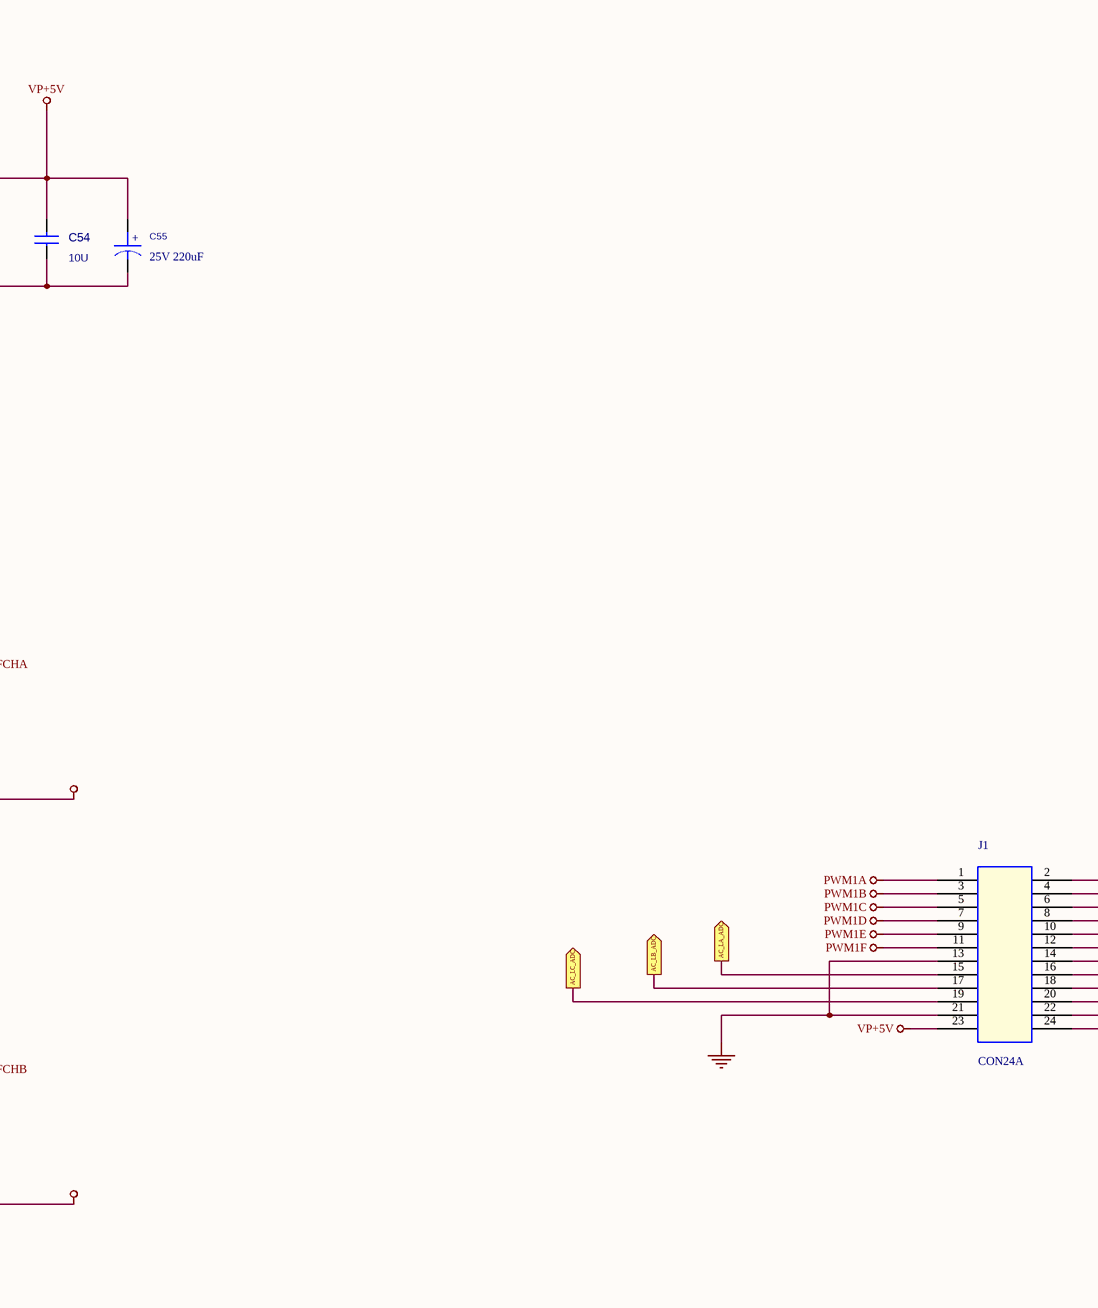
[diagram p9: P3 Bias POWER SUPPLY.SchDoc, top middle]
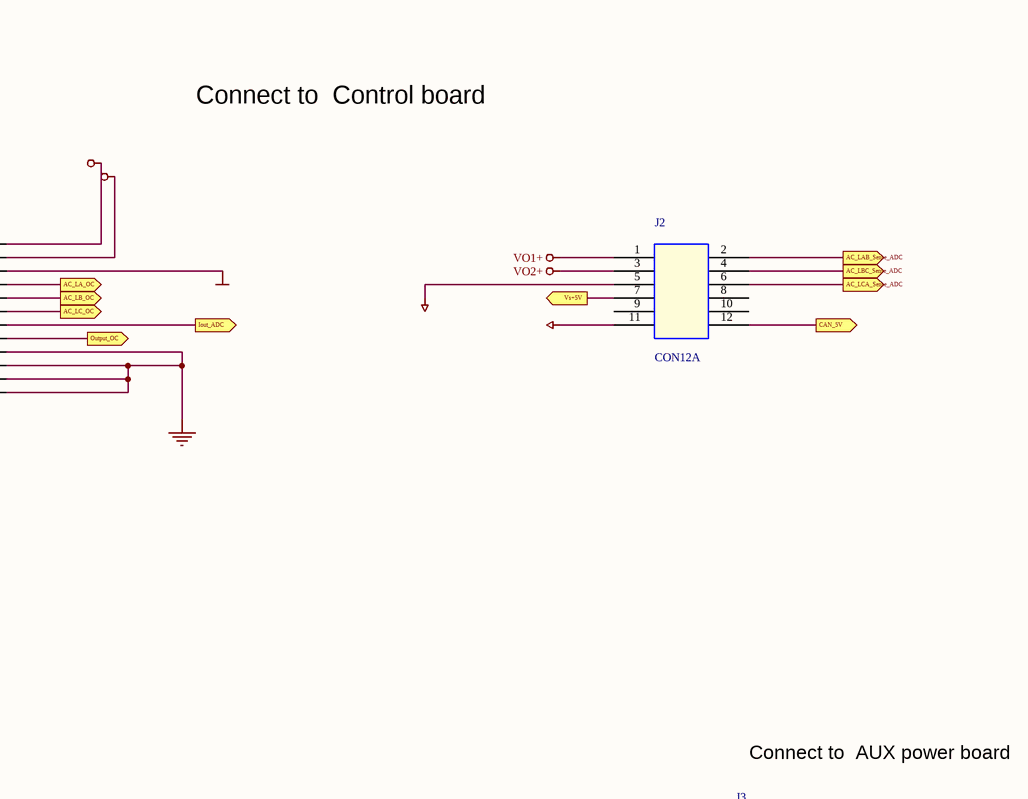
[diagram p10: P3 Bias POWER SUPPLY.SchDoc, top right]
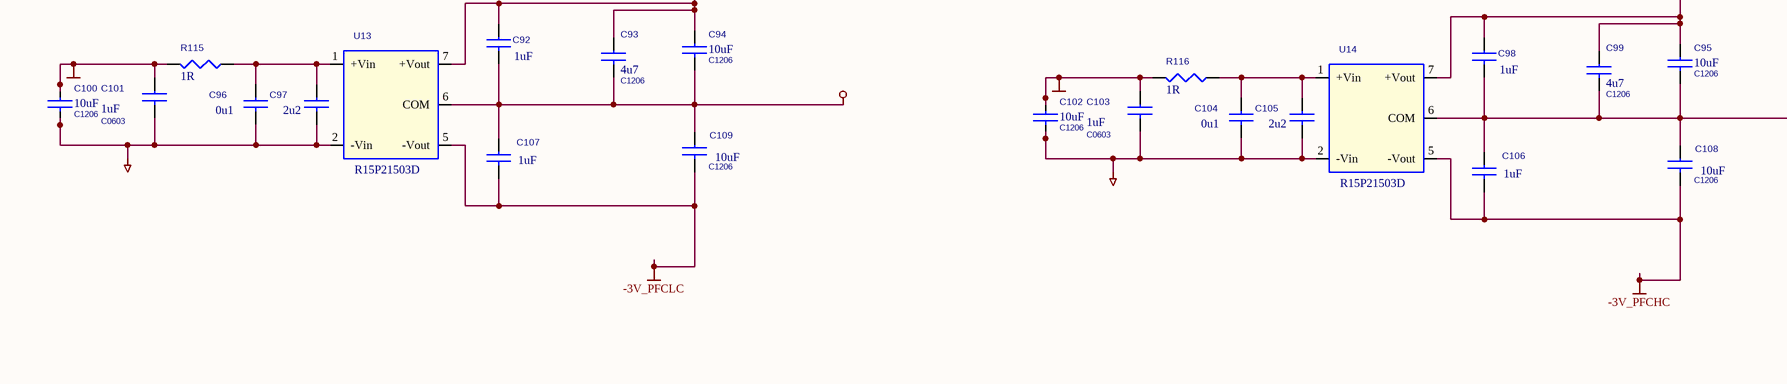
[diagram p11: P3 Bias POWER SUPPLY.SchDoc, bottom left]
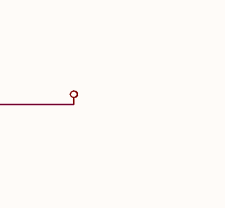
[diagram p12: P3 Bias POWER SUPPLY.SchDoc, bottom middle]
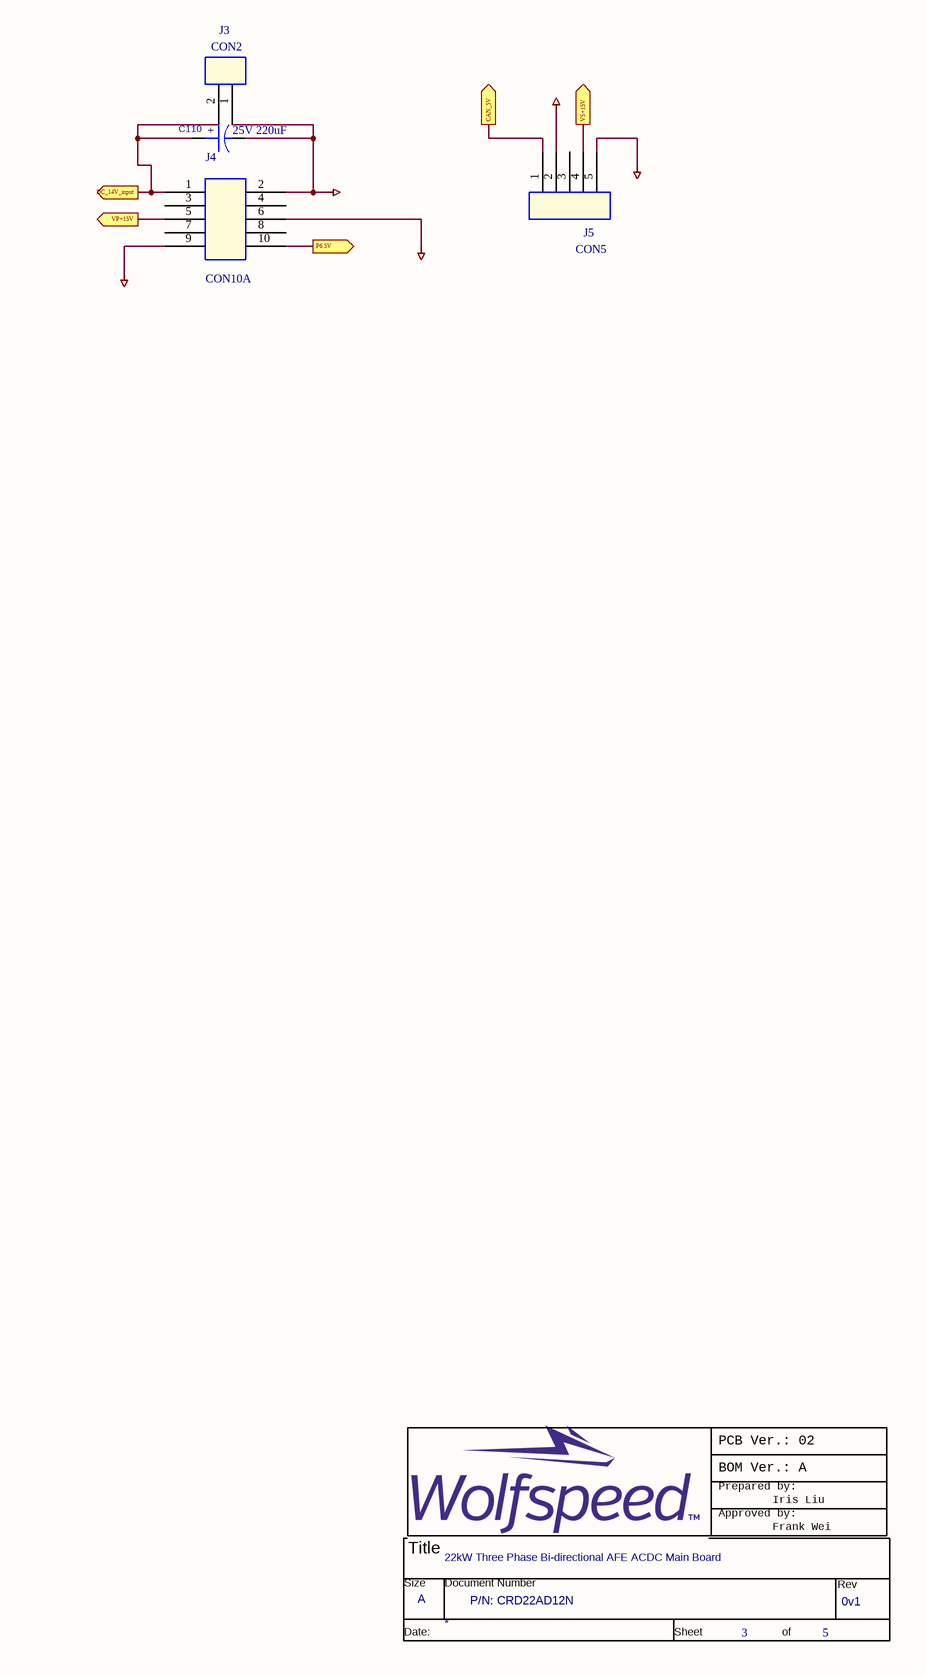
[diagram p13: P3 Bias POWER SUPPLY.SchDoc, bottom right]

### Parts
(Parts that share a designator on the sheet are numbered #1, #2 ... from top to bottom, then left to right.)
*#3  Doc: P/N: CRD22AD12N  RevCode: 0v1  Title: 22kW Three Phase Bi-directional AFE ACDC Main Board  Page Size: A  Page Number: 3  Page Count: 5  (hidden comment: TitleBlock0_cree_power)  (graphical)
C45  10U  [C1206]
C46  1U  [C0603]
C47  10U  [C1206]
C48  1U  [C0603]
C49  1U  [C1206]
C50  22u  [C1206]
C51  22u  [C1206]
C52  10U  [C1206]
C53  10U  [C1206]
C54  10U  [C1206]
C55  25V 220uF  [ecap_d8p3_5]
C56  1uF  [C0603]
C57  4u7  [C1206]
C58  10uF  [C1206]
C59  1uF  [C0603]
C60  4u7  [C1206]
C61  10uF  [C1206]
C62  10uF  [C1206]
C63  1uF  [C0603]
C64  0u1  [C0603]
C65  2u2  [C1206]
C66  10uF  [C1206]
C67  1uF  [C0603]
C68  0u1  [C0603]
C69  2u2  [C1206]
C70  1uF  [C0603]
C71  1uF  [C0603]
C72  10uF  [C1206]
C73  10uF  [C1206]
C74  1uF  [C0603]
C75  4u7  [C1206]
C76  10uF  [C1206]
C77  10uF  [C1206]
C78  0u1  [C0603]
C79  2u2  [C1206]
C80  1uF  [C0603]
C81  4u7  [C1206]
C82  10uF  [C1206]
C83  1uF  [C0603]
C84  10uF  [C1206]
C85  1uF  [C0603]
C86  0u1  [C0603]
C87  2u2  [C1206]
C88  1uF  [C0603]
C89  1uF  [C0603]
C90  10uF  [C1206]
C91  10uF  [C1206]
C92  1uF  [C0603]
C93  4u7  [C1206]
C94  10uF  [C1206]
C95  10uF  [C1206]
C96  0u1  [C0603]
C97  2u2  [C1206]
C98  1uF  [C0603]
C99  4u7  [C1206]
C100  10uF  [C1206]
C101  1uF  [C0603]
C102  10uF  [C1206]
C103  1uF  [C0603]
C104  0u1  [C0603]
C105  2u2  [C1206]
C106  1uF  [C0603]
C107  1uF  [C0603]
C108  10uF  [C1206]
C109  10uF  [C1206]
C110  25V 220uF  [ecap_d8p3_5]
J1  CON24A  [con_2mm54_12x2]
J2  CON12A  [con_2mm54_6x2]
J3  CON2  [CON_5MM_2X1]
J4  CON10A  [con_2mm54_5x2]
J5  CON5  [con_2mm54_5x1]
R111  1R  [R0805]
R112  1R  [R0805]
R113  1R  [R0805]
R114  1R  [R0805]
R115  1R  [R0805]
R116  1R  [R0805]
U7  MC78L05F-TP  [SOT-89-3L]
U8  LF50ABDT-TR  [TO252AB]
U9  R15P21503D  [g1212s_2w11]
U10  R15P21503D  [g1212s_2w11]
U11  R15P21503D  [g1212s_2w11]
U12  R15P21503D  [g1212s_2w11]
U13  R15P21503D  [g1212s_2w11]
U14  R15P21503D  [g1212s_2w11]

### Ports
AC_LA_ADC (out), AC_LA_OC (out), AC_LAB_Sense_ADC (out), AC_LB_ADC (out), AC_LB_OC (out), AC_LBC_Sense_ADC (out), AC_LC_ADC (out), AC_LC_OC (out), AC_LCA_Sense_ADC (out), CAN_5V (out), DC_14V_input (out), Iout_ADC (out), Output_OC (out), P6.5V (out), VP+15V (out), Vs+5V (out), VS+15V (out)

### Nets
-3V_PFCHA: C71.2 C72.2 U10.5(-Vout)
-3V_PFCHB: C88.2 C90.2 U12.5(-Vout)
-3V_PFCHC: C106.2 C108.2 U14.5(-Vout)
-3V_PFCLA: C70.2 C73.2 U9.5(-Vout)
-3V_PFCLB: C89.2 C91.2 U11.5(-Vout)
-3V_PFCLC: C107.2 C109.2 U13.5(-Vout)
AGND: C47.1 C48.1 C52.1 C53.1 C54.1 C55.2 J1.13 J1.18 J1.20 J1.21 J1.22 J1.24 J4.9 U8.2(GND)
CAN5V_GND: J2.11 J5.2
GGND: C62.2 C63.2 C64.2 C65.2 C66.2 C67.2 C68.2 C69.2 C78.2 C79.2 C82.2 C83.2 C84.2 C85.2 C86.2 C87.2 C96.2 C97.2 C100.2 C101.2 C102.2 C103.2 C104.2 C105.2 J4.6 U9.2(-Vin) U10.2(-Vin) U11.2(-Vin) U12.2(-Vin) U13.2(-Vin) U14.2(-Vin)
IGND: C110.2 J3.1 J4.2
PFC_G_HA: C59.2 C60.2 C61.2 C71.1 C72.1 U10.6(COM)
PFC_G_HB: C77.2 C80.2 C81.2 C88.1 C90.1 U12.6(COM)
PFC_G_HC: C95.2 C98.2 C99.2 C106.1 C108.1 U14.6(COM)
PFC_G_LA: C56.2 C57.2 C58.2 C70.1 C73.1 U9.6(COM)
PFC_G_LB: C74.2 C75.2 C76.2 C89.1 C91.1 U11.6(COM)
PFC_G_LC: C92.2 C93.2 C94.2 C107.1 C109.1 U13.6(COM)
PGND: C45.1 C46.1 C49.1 C50.1 C51.1 J2.5 J5.5 U7.2(GND)
PWM1A: J1.1
PWM1B: J1.3
PWM1C: J1.5
PWM1D: J1.7
PWM1E: J1.9
PWM1F: J1.11
RLYCTRL1: J1.2
RLYCTRL2: J1.4
VO1+: J2.1
VO2+: J2.3
VP3.3D: J1.6
VP+5V: C53.2 C54.2 C55.1 J1.23 U8.1(Vout)
VP+15V: C62.1 C63.1 C66.1 C67.1 C82.1 C83.1 C84.1 C85.1 C100.1 C101.1 C102.1 C103.1 R111.2 R112.2 R113.2 R114.2 R115.2 R116.2
VP+15V_PFCHA: C59.1 C60.1 C61.1 U10.7(+Vout)
VP+15V_PFCHB: C77.1 C80.1 C81.1 U12.7(+Vout)
VP+15V_PFCHC: C95.1 C98.1 C99.1 U14.7(+Vout)
VP+15V_PFCLA: C56.1 C57.1 C58.1 U9.7(+Vout)
VP+15V_PFCLB: C74.1 C75.1 C76.1 U11.7(+Vout)
VP+15V_PFCLC: C92.1 C93.1 C94.1 U13.7(+Vout)
NetC45_2: C45.2 C46.2 J5.4 U7.3(Vin) ; port VS+15V
NetC47_2: C47.2 C48.2 C52.2 J4.10 U8.3(Vin) ; port P6.5V
NetC49_2: C49.2 C50.2 C51.2 J2.7 U7.1(Vout) ; port Vs+5V
NetC64_1: C64.1 C65.1 R111.1 U9.1(+Vin)
NetC68_1: C68.1 C69.1 R112.1 U10.1(+Vin)
NetC78_1: C78.1 C79.1 R113.1 U11.1(+Vin)
NetC86_1: C86.1 C87.1 R114.1 U12.1(+Vin)
NetC96_1: C96.1 C97.1 R115.1 U13.1(+Vin)
NetC104_1: C104.1 C105.1 R116.1 U14.1(+Vin)
NetC110_1: C110.1 J3.2 J4.1 ; port DC_14V_input
NetC214_2: J2.2 ; port AC_LAB_Sense_ADC
NetC217_2: J2.4 ; port AC_LBC_Sense_ADC
NetC219_2: J2.6 ; port AC_LCA_Sense_ADC
NetJ1_8: J1.8 ; port AC_LA_OC
NetJ1_10: J1.10 ; port AC_LB_OC
NetJ1_12: J1.12 ; port AC_LC_OC
NetJ1_14: J1.14 ; port Iout_ADC
NetJ1_15: J1.15 ; port AC_LA_ADC
NetJ1_16: J1.16 ; port Output_OC
NetJ1_17: J1.17 ; port AC_LB_ADC
NetJ1_19: J1.19 ; port AC_LC_ADC
NetJ2_12: J2.12 J5.1 ; port CAN_5V
NetJ4_5: J4.5 ; port VP+15V

Not connected (* = marked no-connect by the designer): J2 8 9 10; J4 3 4 7 8; J5 3

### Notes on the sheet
- 12V--->+5V
- 6.5V--->+5V for control
- PFC power supply for gate driver
- Connect to  Control board
- Connect to  AUX power board
- PCB Ver.: 02
- BOM Ver.: A
- Prepared by:
- Approved by:
- .
- Frank Wei
- Iris Liu

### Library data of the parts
C45-C54 = CAP NP_Dup1
C55 C110 = CAP POL
C56-C109 = CAP NP
R111-R116 = RESISTOR
U8 = MC78L05F-TP
U9-U14 = E1212S-2WR2_3

## Sheet P4 PFC Gate Driver.SchDoc
size 594 x 420 mm
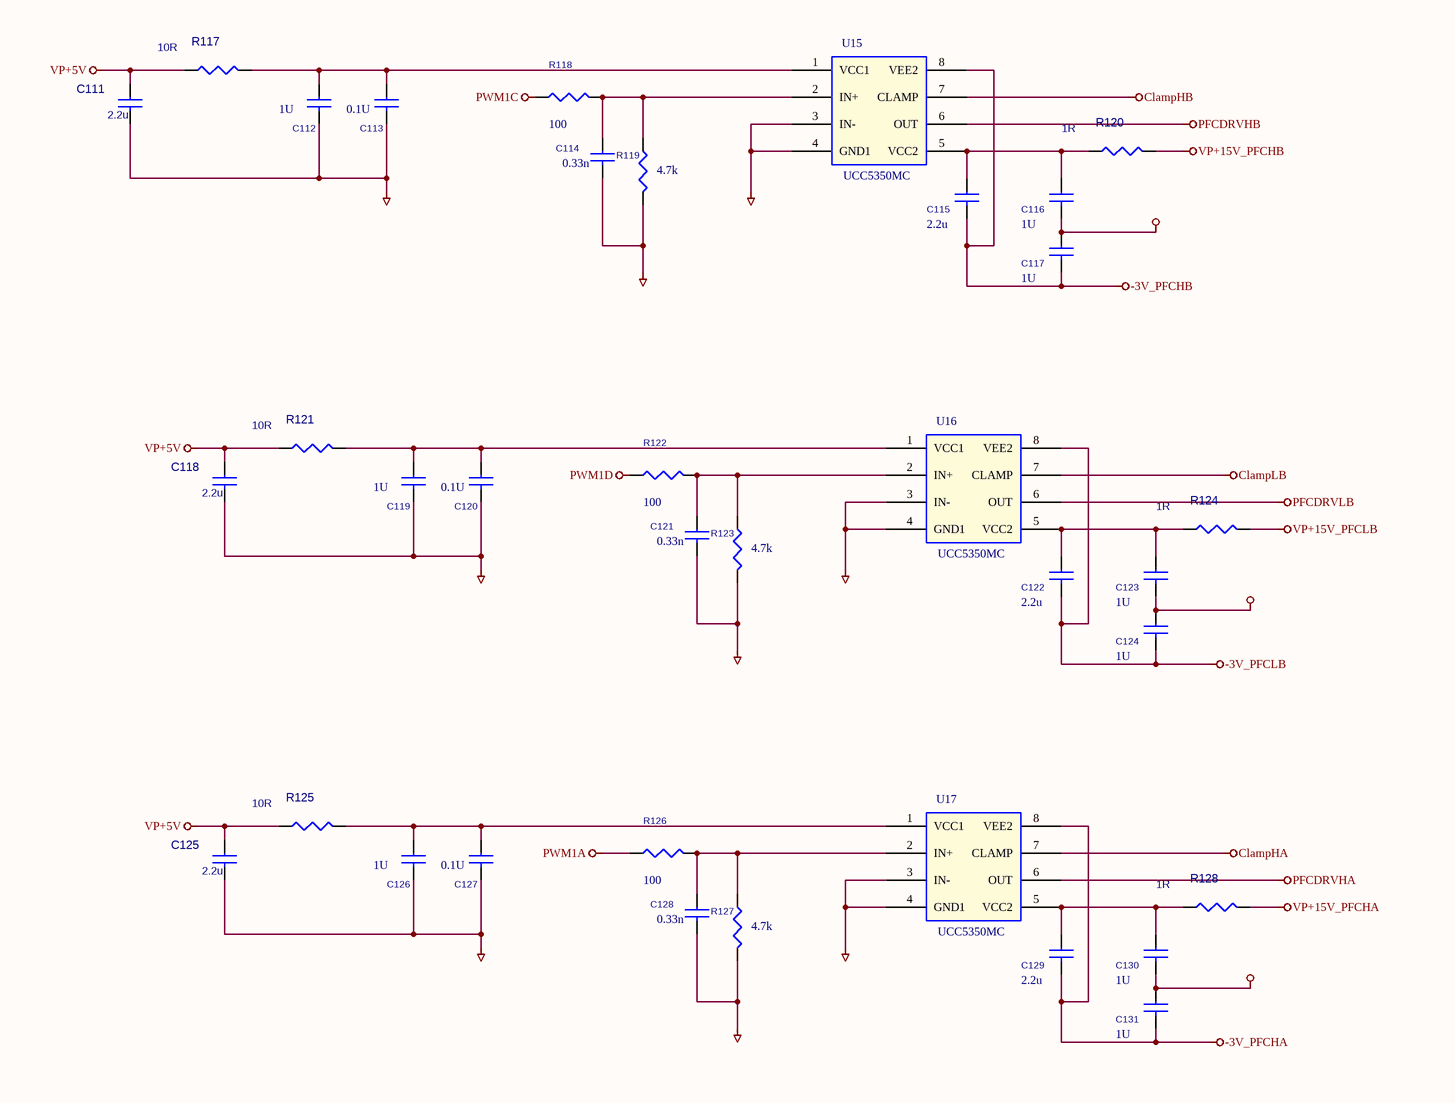
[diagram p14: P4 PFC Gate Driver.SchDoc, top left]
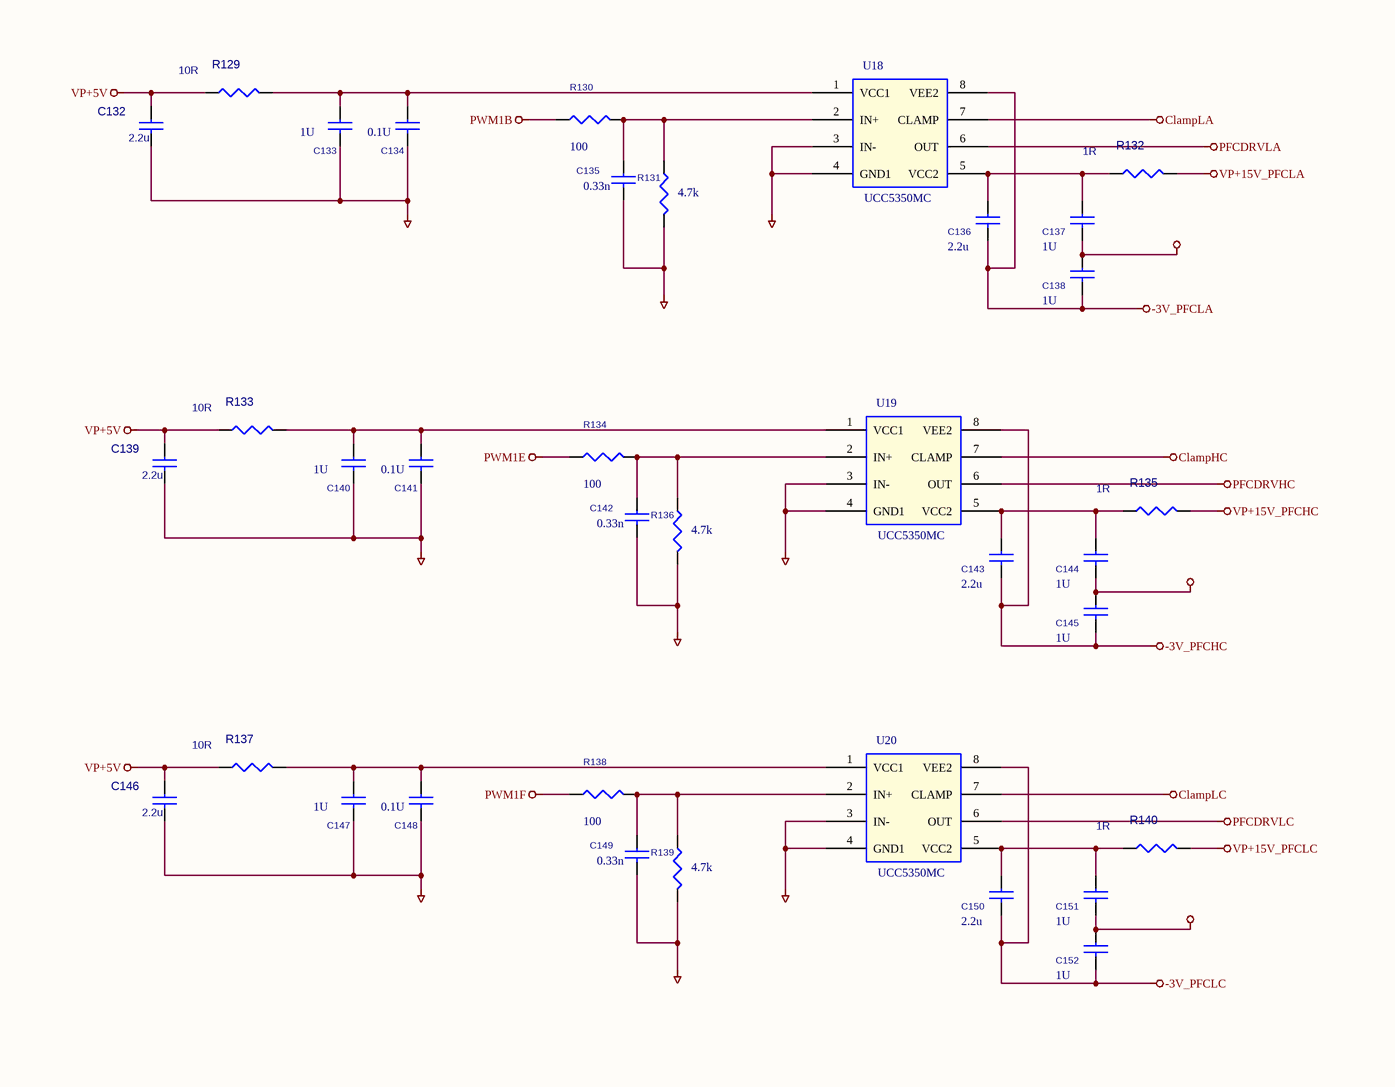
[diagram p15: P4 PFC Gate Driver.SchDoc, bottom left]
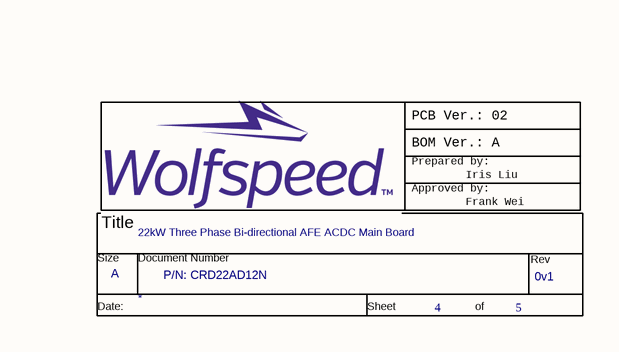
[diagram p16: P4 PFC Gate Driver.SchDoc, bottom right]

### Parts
(Parts that share a designator on the sheet are numbered #1, #2 ... from top to bottom, then left to right.)
*#4  Doc: P/N: CRD22AD12N  RevCode: 0v1  Title: 22kW Three Phase Bi-directional AFE ACDC Main Board  Page Size: A  Page Number: 4  Page Count: 5  (hidden comment: TitleBlock0_cree_power)  (graphical)
C111  2.2u  [C0603]
C112  1U  [C0603]
C113  0.1U  [C0603]
C114  0.33n  [C0603]
C115  2.2u  [C0805]
C116  1U  [C0603]
C117  1U  [C0603]
C118  2.2u  [C0603]
C119  1U  [C0603]
C120  0.1U  [C0603]
C121  0.33n  [C0603]
C122  2.2u  [C0805]
C123  1U  [C0603]
C124  1U  [C0603]
C125  2.2u  [C0603]
C126  1U  [C0603]
C127  0.1U  [C0603]
C128  0.33n  [C0603]
C129  2.2u  [C0805]
C130  1U  [C0603]
C131  1U  [C0603]
C132  2.2u  [C0603]
C133  1U  [C0603]
C134  0.1U  [C0603]
C135  0.33n  [C0603]
C136  2.2u  [C0805]
C137  1U  [C0603]
C138  1U  [C0603]
C139  2.2u  [C0603]
C140  1U  [C0603]
C141  0.1U  [C0603]
C142  0.33n  [C0603]
C143  2.2u  [C0805]
C144  1U  [C0603]
C145  1U  [C0603]
C146  2.2u  [C0603]
C147  1U  [C0603]
C148  0.1U  [C0603]
C149  0.33n  [C0603]
C150  2.2u  [C0805]
C151  1U  [C0603]
C152  1U  [C0603]
R117  10R  [R0603]
R118  100  [R0603]
R119  4.7k  [R0603]
R120  1R  [R0805]
R121  10R  [R0603]
R122  100  [R0603]
R123  4.7k  [R0603]
R124  1R  [R0805]
R125  10R  [R0603]
R126  100  [R0603]
R127  4.7k  [R0603]
R128  1R  [R0805]
R129  10R  [R0603]
R130  100  [R0603]
R131  4.7k  [R0603]
R132  1R  [R0805]
R133  10R  [R0603]
R134  100  [R0603]
R135  1R  [R0805]
R136  4.7k  [R0603]
R137  10R  [R0603]
R138  100  [R0603]
R139  4.7k  [R0603]
R140  1R  [R0805]
U15  UCC5350MC  [SOIC8_DWV]
U16  UCC5350MC  [SOIC8_DWV]
U17  UCC5350MC  [SOIC8_DWV]
U18  UCC5350MC  [SOIC8_DWV]
U19  UCC5350MC  [SOIC8_DWV]
U20  UCC5350MC  [SOIC8_DWV]

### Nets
-3V_PFCHA: C129.2 C131.2 U17.8(VEE2)
-3V_PFCHB: C115.2 C117.2 U15.8(VEE2)
-3V_PFCHC: C143.2 C145.2 U19.8(VEE2)
-3V_PFCLA: C136.2 C138.2 U18.8(VEE2)
-3V_PFCLB: C122.2 C124.2 U16.8(VEE2)
-3V_PFCLC: C150.2 C152.2 U20.8(VEE2)
AGND: C111.2 C112.2 C113.2 C114.2 C118.2 C119.2 C120.2 C121.2 C125.2 C126.2 C127.2 C128.2 C132.2 C133.2 C134.2 C135.2 C139.2 C140.2 C141.2 C142.2 C146.2 C147.2 C148.2 C149.2 R119.2 R123.2 R127.2 R131.2 R136.2 R139.2 U15.3(IN-) U15.4(GND1) U16.3(IN-) U16.4(GND1) U17.3(IN-) U17.4(GND1) U18.3(IN-) U18.4(GND1) U19.3(IN-) U19.4(GND1) U20.3(IN-) U20.4(GND1)
ClampHA: U17.7(CLAMP)
ClampHB: U15.7(CLAMP)
ClampHC: U19.7(CLAMP)
ClampLA: U18.7(CLAMP)
ClampLB: U16.7(CLAMP)
ClampLC: U20.7(CLAMP)
PFC_G_HA: C130.2 C131.1
PFC_G_HB: C116.2 C117.1
PFC_G_HC: C144.2 C145.1
PFC_G_LA: C137.2 C138.1
PFC_G_LB: C123.2 C124.1
PFC_G_LC: C151.2 C152.1
PFCDRVHA: U17.6(OUT)
PFCDRVHB: U15.6(OUT)
PFCDRVHC: U19.6(OUT)
PFCDRVLA: U18.6(OUT)
PFCDRVLB: U16.6(OUT)
PFCDRVLC: U20.6(OUT)
PWM1A: R126.1
PWM1B: R130.1
PWM1C: R118.1
PWM1D: R122.1
PWM1E: R134.1
PWM1F: R138.1
VP+5V: C111.1 C118.1 C125.1 C132.1 C139.1 C146.1 R117.1 R121.1 R125.1 R129.1 R133.1 R137.1
VP+15V_PFCHA: R128.2
VP+15V_PFCHB: R120.2
VP+15V_PFCHC: R135.2
VP+15V_PFCLA: R132.2
VP+15V_PFCLB: R124.2
VP+15V_PFCLC: R140.2
NetC112_1: C112.1 C113.1 R117.2 U15.1(VCC1)
NetC114_1: C114.1 R118.2 R119.1 U15.2(IN+)
NetC115_1: C115.1 C116.1 R120.1 U15.5(VCC2)
NetC119_1: C119.1 C120.1 R121.2 U16.1(VCC1)
NetC121_1: C121.1 R122.2 R123.1 U16.2(IN+)
NetC122_1: C122.1 C123.1 R124.1 U16.5(VCC2)
NetC126_1: C126.1 C127.1 R125.2 U17.1(VCC1)
NetC128_1: C128.1 R126.2 R127.1 U17.2(IN+)
NetC129_1: C129.1 C130.1 R128.1 U17.5(VCC2)
NetC133_1: C133.1 C134.1 R129.2 U18.1(VCC1)
NetC135_1: C135.1 R130.2 R131.1 U18.2(IN+)
NetC136_1: C136.1 C137.1 R132.1 U18.5(VCC2)
NetC140_1: C140.1 C141.1 R133.2 U19.1(VCC1)
NetC142_1: C142.1 R134.2 R136.1 U19.2(IN+)
NetC143_1: C143.1 C144.1 R135.1 U19.5(VCC2)
NetC147_1: C147.1 C148.1 R137.2 U20.1(VCC1)
NetC149_1: C149.1 R138.2 R139.1 U20.2(IN+)
NetC150_1: C150.1 C151.1 R140.1 U20.5(VCC2)

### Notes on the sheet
- PCB Ver.: 02
- BOM Ver.: A
- Prepared by:
- Approved by:
- .
- Frank Wei
- Iris Liu

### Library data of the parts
C111 C118 C125 C132 C139 C146 = CAP NP_Dup1
C112-C117 C119-C124 C126-C131 C133-C138 C140-C145 C147-C152 = CAP NP
R117 R120 R121 R124 R125 R128 R129 R132 R133 R135 R137 R140 = R
R118 R119 R122 R123 R126 R127 R130 R131 R134 R136 R138 R139 = RESISTOR

## Sheet P5 PFC sampling.SchDoc
size 420 x 297 mm
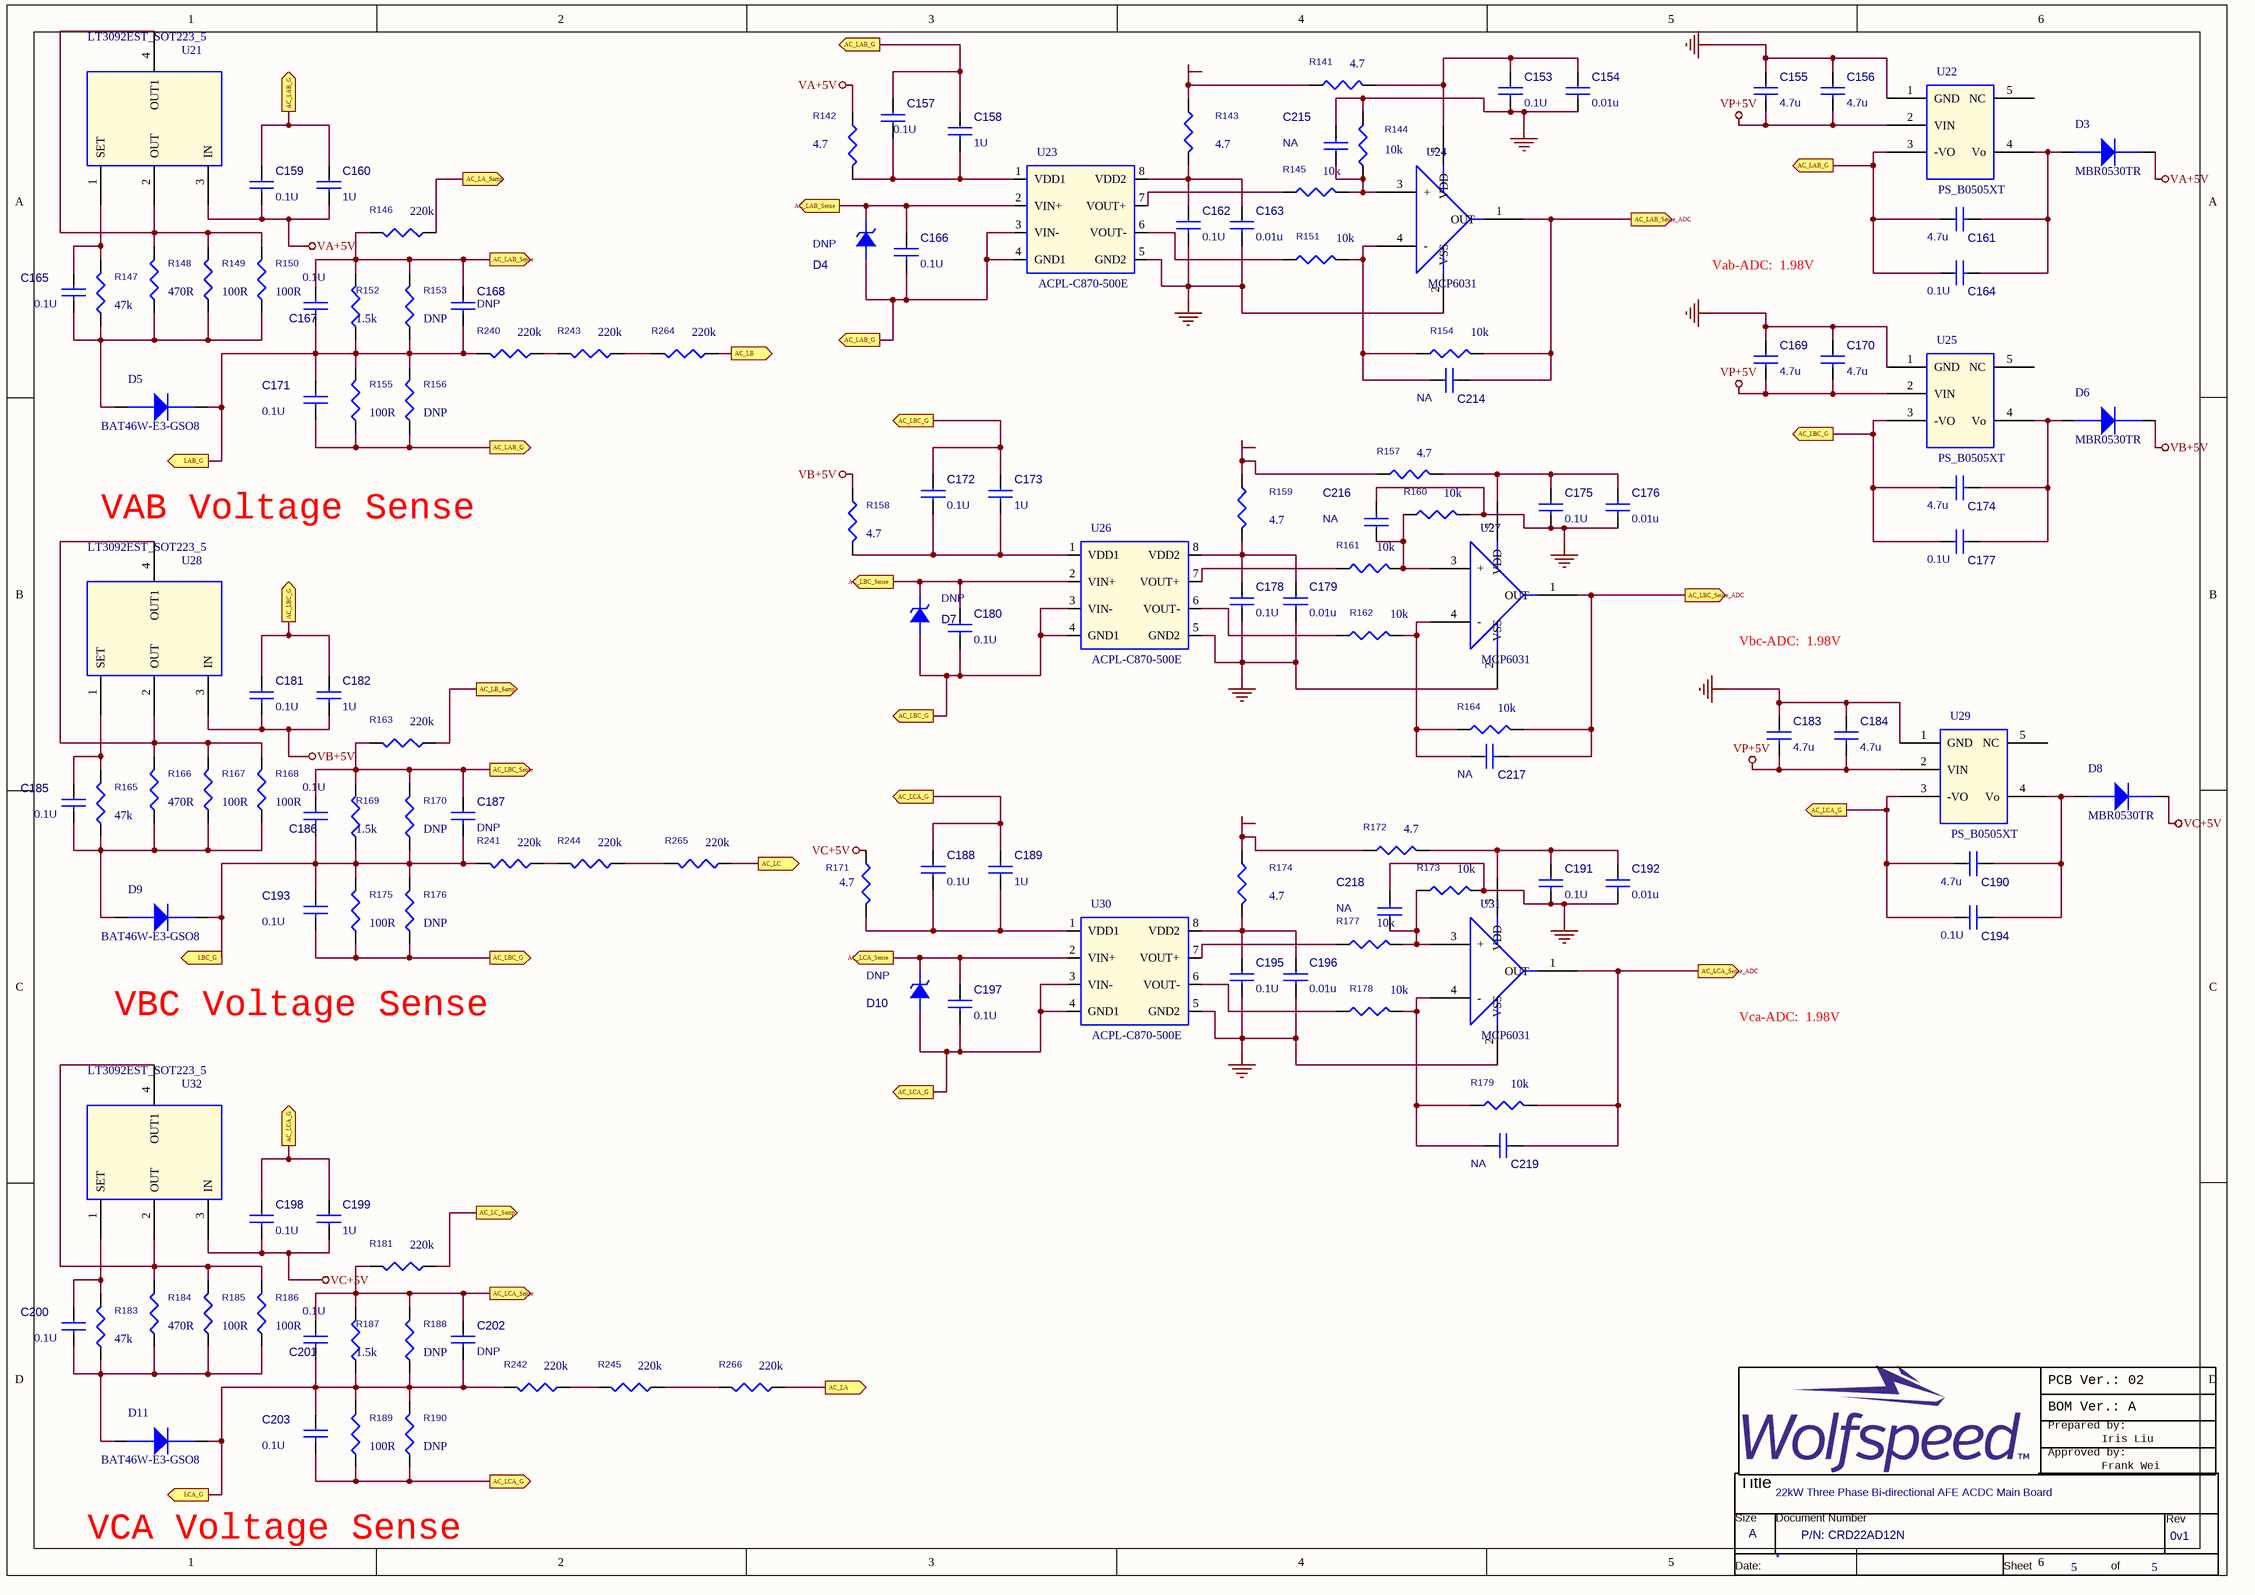
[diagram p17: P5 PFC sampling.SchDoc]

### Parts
(Parts that share a designator on the sheet are numbered #1, #2 ... from top to bottom, then left to right.)
*#5  Doc: P/N: CRD22AD12N  RevCode: 0v1  Title: 22kW Three Phase Bi-directional AFE ACDC Main Board  Page Size: A  Page Number: 5  (hidden comment: TitleBlock0_cree_power)  (graphical)
C153  0.1U  [C0603]
C154  0.01u  [C0603]
C155  4.7u  [C0805]
C156  4.7u  [C0805]
C157  0.1U  [C0603]
C158  1U  [C0603]
C159  0.1U  [C0603]
C160  1U  [C0603]
C161  4.7u  [C0805]
C162  0.1U  [C0603]
C163  0.01u  [C0603]
C164  0.1U  [C0603]
C165  0.1U  [C0603]
C166  0.1U  [C0603]
C167  0.1U  [C0603]
C168  DNP  [C0603]
C169  4.7u  [C0805]
C170  4.7u  [C0805]
C171  0.1U  [C0603]
C172  0.1U  [C0603]
C173  1U  [C0603]
C174  4.7u  [C0805]
C175  0.1U  [C0603]
C176  0.01u  [C0603]
C177  0.1U  [C0603]
C178  0.1U  [C0603]
C179  0.01u  [C0603]
C180  0.1U  [C0603]
C181  0.1U  [C0603]
C182  1U  [C0603]
C183  4.7u  [C0805]
C184  4.7u  [C0805]
C185  0.1U  [C0603]
C186  0.1U  [C0603]
C187  DNP  [C0603]
C188  0.1U  [C0603]
C189  1U  [C0603]
C190  4.7u  [C0805]
C191  0.1U  [C0603]
C192  0.01u  [C0603]
C193  0.1U  [C0603]
C194  0.1U  [C0603]
C195  0.1U  [C0603]
C196  0.01u  [C0603]
C197  0.1U  [C0603]
C198  0.1U  [C0603]
C199  1U  [C0603]
C200  0.1U  [C0603]
C201  0.1U  [C0603]
C202  DNP  [C0603]
C203  0.1U  [C0603]
C214  NA  [C0603]
C215  NA  [C0603]
C216  NA  [C0603]
C217  NA  [C0603]
C218  NA  [C0603]
C219  NA  [C0603]
D3  MBR0530TR  [SOD-123]
D4  DNP  [SOD-123]
D5  BAT46W-E3-GSO8  [SOD-123]
D6  MBR0530TR  [SOD-123]
D7  DNP  [SOD-123]
D8  MBR0530TR  [SOD-123]
D9  BAT46W-E3-GSO8  [SOD-123]
D10  DNP  [SOD-123]
D11  BAT46W-E3-GSO8  [SOD-123]
R141  4.7  [R0603]
R142  4.7  [R0603]
R143  4.7  [R0603]
R144  10k  [R0603]
R145  10k  [R0603]
R146  220k  [R1206]
R147  47k  [R0603]
R148  470R  [R0603]
R149  100R  [R0603]
R150  100R  [R0603]
R151  10k  [R0603]
R152  1.5k  [R1206]
R153  DNP  [R0603]
R154  10k  [R0603]
R155  100R  [R0603]
R156  DNP  [R0603]
R157  4.7  [R0603]
R158  4.7  [R0603]
R159  4.7  [R0603]
R160  10k  [R0603]
R161  10k  [R0603]
R162  10k  [R0603]
R163  220k  [R1206]
R164  10k  [R0603]
R165  47k  [R0603]
R166  470R  [R0603]
R167  100R  [R0603]
R168  100R  [R0603]
R169  1.5k  [R1206]
R170  DNP  [R0603]
R171  4.7  [R0603]
R172  4.7  [R0603]
R173  10k  [R0603]
R174  4.7  [R0603]
R175  100R  [R0603]
R176  DNP  [R0603]
R177  10k  [R0603]
R178  10k  [R0603]
R179  10k  [R0603]
R181  220k  [R1206]
R183  47k  [R0603]
R184  470R  [R0603]
R185  100R  [R0603]
R186  100R  [R0603]
R187  1.5k  [R1206]
R188  DNP  [R0603]
R189  100R  [R0603]
R190  DNP  [R0603]
R240  220k  [R1206]
R241  220k  [R1206]
R242  220k  [R1206]
R243  220k  [R1206]
R244  220k  [R1206]
R245  220k  [R1206]
R264  220k  [R1206]
R265  220k  [R1206]
R266  220k  [R1206]
U21  LT3092EST_SOT223_5  [SOT223_3]
U22  PS_B0505XT  [SMD-5]
U23  ACPL-C870-500E  [SSO-8]
U24  MCP6031  [SOT23-5]
U25  PS_B0505XT  [SMD-5]
U26  ACPL-C870-500E  [SSO-8]
U27  MCP6031  [SOT23-5]
U28  LT3092EST_SOT223_5  [SOT223_3]
U29  PS_B0505XT  [SMD-5]
U30  ACPL-C870-500E  [SSO-8]
U31  MCP6031  [SOT23-5]
U32  LT3092EST_SOT223_5  [SOT223_3]

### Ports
AC_LA (out), AC_LA_Samp (out), AC_LAB_G (out), AC_LAB_Sense (out), AC_LAB_Sense_ADC (out), AC_LB (out), AC_LB_Samp (out), AC_LBC_G (out), AC_LBC_Sense (out), AC_LBC_Sense_ADC (out), AC_LC (out), AC_LC_Samp (out), AC_LCA_G (out), AC_LCA_Sense (out), AC_LCA_Sense_ADC (out), LAB_G (out), LBC_G (out), LCA_G (out)

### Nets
AGND: C153.2 C154.2 C155.1 C156.1 C162.2 C163.2 C169.1 C170.1 C175.2 C176.2 C178.2 C179.2 C183.1 C184.1 C191.2 C192.2 C195.2 C196.2 C215.2 C216.2 C218.2 R144.2 R160.2 R173.2 U22.1(GND) U23.5(GND2) U24.2(VSS) U25.1(GND) U26.5(GND2) U27.2(VSS) U29.1(GND) U30.5(GND2) U31.2(VSS)
VA+5V: C159.2 C160.2 D3.2(CATHODE) R142.1 U21.3(IN)
VB+5V: C181.2 C182.2 D6.2(CATHODE) R158.1 U28.3(IN)
VC+5V: C198.2 C199.2 D8.2(CATHODE) R171.1 U32.3(IN)
VP3.3D: R141.1 R143.1 R157.1 R159.1 R172.1 R174.1
VP+5V: C155.2 C156.2 C169.2 C170.2 C183.2 C184.2 U22.2(VIN) U25.2(VIN) U29.2(VIN)
NetC153_1: C153.1 C154.1 R141.2 U24.5(VDD)
NetC157_1: C157.1 C158.1 C159.1 C160.1 C161.1 C164.1 C166.2 C171.2 D4.1(ANODE) R155.1 R156.1 U22.3(-VO) U23.3(VIN-) U23.4(GND1) ; port AC_LAB_G
NetC157_2: C157.2 C158.2 R142.2 U23.1(VDD1)
NetC161_2: C161.2 C164.2 D3.1(ANODE) U22.4(Vo)
NetC162_1: C162.1 C163.1 R143.2 U23.8(VDD2)
NetC165_1: C165.1 R147.2 U21.1(SET)
NetC165_2: C165.2 D5.1(ANODE) R147.1 R148.1 R149.1 R150.1
NetC166_1: C166.1 C167.1 C168.1 D4.2(CATHODE) R146.2 R152.2 R153.2 U23.2(VIN+) ; port AC_LAB_Sense
NetC167_2: C167.2 C168.2 C171.1 D5.2(CATHODE) R152.1 R153.1 R155.2 R156.2 R240.2 ; port LAB_G
NetC172_1: C172.1 C173.1 C174.1 C177.1 C180.2 C181.1 C182.1 C193.2 D7.1(ANODE) R175.1 R176.1 U25.3(-VO) U26.3(VIN-) U26.4(GND1) ; port AC_LBC_G
NetC172_2: C172.2 C173.2 R158.2 U26.1(VDD1)
NetC174_2: C174.2 C177.2 D6.1(ANODE) U25.4(Vo)
NetC175_1: C175.1 C176.1 R157.2 U27.5(VDD)
NetC178_1: C178.1 C179.1 R159.2 U26.8(VDD2)
NetC180_1: C180.1 C186.1 C187.1 D7.2(CATHODE) R163.2 R169.2 R170.2 U26.2(VIN+) ; port AC_LBC_Sense
NetC185_1: C185.1 R165.2 U28.1(SET)
NetC185_2: C185.2 D9.1(ANODE) R165.1 R166.1 R167.1 R168.1
NetC186_2: C186.2 C187.2 C193.1 D9.2(CATHODE) R169.1 R170.1 R175.2 R176.2 R241.2 ; port LBC_G
NetC188_1: C188.1 C189.1 C190.1 C194.1 C197.2 C198.1 C199.1 C203.2 D10.1(ANODE) R189.1 R190.1 U29.3(-VO) U30.3(VIN-) U30.4(GND1) ; port AC_LCA_G
NetC188_2: C188.2 C189.2 R171.2 U30.1(VDD1)
NetC190_2: C190.2 C194.2 D8.1(ANODE) U29.4(Vo)
NetC191_1: C191.1 C192.1 R172.2 U31.5(VDD)
NetC195_1: C195.1 C196.1 R174.2 U30.8(VDD2)
NetC197_1: C197.1 C201.1 C202.1 D10.2(CATHODE) R181.2 R187.2 R188.2 U30.2(VIN+) ; port AC_LCA_Sense
NetC200_1: C200.1 R183.2 U32.1(SET)
NetC200_2: C200.2 D11.1(ANODE) R183.1 R184.1 R185.1 R186.1
NetC201_2: C201.2 C202.2 C203.1 D11.2(CATHODE) R187.1 R188.1 R189.2 R190.2 R242.2 ; port LCA_G
NetC214_1: C214.1 R151.2 R154.1 U24.4(-)
NetC214_2: C214.2 R154.2 U24.1(OUT) ; port AC_LAB_Sense_ADC
NetC215_1: C215.1 R144.1 R145.2 U24.3(+)
NetC216_1: C216.1 R160.1 R161.2 U27.3(+)
NetC217_1: C217.1 R162.2 R164.1 U27.4(-)
NetC217_2: C217.2 R164.2 U27.1(OUT) ; port AC_LBC_Sense_ADC
NetC218_1: C218.1 R173.1 R177.2 U31.3(+)
NetC219_1: C219.1 R178.2 R179.1 U31.4(-)
NetC219_2: C219.2 R179.2 U31.1(OUT) ; port AC_LCA_Sense_ADC
NetCL2_A1_2: R265.1 ; port AC_LC
NetCL2_A1_4: R264.1 ; port AC_LB
NetCL2_A1_6: R266.1 ; port AC_LA
NetR29_2: R146.1 ; port AC_LA_Samp
NetR38_2: R163.1 ; port AC_LB_Samp
NetR46_2: R181.1 ; port AC_LC_Samp
NetR145_1: R145.1 U23.7(VOUT+)
NetR148_2: R148.2 R149.2 R150.2 U21.2(OUT) U21.4(OUT1)
NetR151_1: R151.1 U23.6(VOUT-)
NetR161_1: R161.1 U26.7(VOUT+)
NetR162_1: R162.1 U26.6(VOUT-)
NetR166_2: R166.2 R167.2 R168.2 U28.2(OUT) U28.4(OUT1)
NetR177_1: R177.1 U30.7(VOUT+)
NetR178_1: R178.1 U30.6(VOUT-)
NetR184_2: R184.2 R185.2 R186.2 U32.2(OUT) U32.4(OUT1)
NetR240_1: R240.1 R243.2
NetR241_1: R241.1 R244.2
NetR242_1: R242.1 R245.2
NetR243_1: R243.1 R264.2
NetR244_1: R244.1 R265.2
NetR245_1: R245.1 R266.2

Not connected (* = marked no-connect by the designer): U22 5(NC); U25 5(NC); U29 5(NC)

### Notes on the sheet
- Vab-ADC:  1.98V
- VAB Voltage Sense
- Vbc-ADC:  1.98V
- VBC Voltage Sense
- Vca-ADC:  1.98V
- PCB Ver.: 02
- Prepared by:
- Approved by:
- BOM Ver.: A
- .
- Frank Wei
- Iris Liu
- VCA Voltage Sense

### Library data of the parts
C153-C203 C214-C219 = CAP NP_Dup1
D3 D5 D6 D8 D9 D11 = BAS21/SOT_1
D4 D7 D10 = DIODE ZENER_0
R141-R179 R181 R183-R190 R240-R245 R264-R266 = RESISTOR
U23 U26 U30 = 24C16BT-I/SN_3

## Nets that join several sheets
-3V_PFCHA: P3 Bias POWER SUPPLY (C71.2 C72.2 U10.5), P4 PFC Gate Driver (C129.2 C131.2 U17.8)
-3V_PFCHB: P3 Bias POWER SUPPLY (C88.2 C90.2 U12.5), P4 PFC Gate Driver (C115.2 C117.2 U15.8)
-3V_PFCHC: P3 Bias POWER SUPPLY (C106.2 C108.2 U14.5), P4 PFC Gate Driver (C143.2 C145.2 U19.8)
-3V_PFCLA: P3 Bias POWER SUPPLY (C70.2 C73.2 U9.5), P4 PFC Gate Driver (C136.2 C138.2 U18.8)
-3V_PFCLB: P3 Bias POWER SUPPLY (C89.2 C91.2 U11.5), P4 PFC Gate Driver (C122.2 C124.2 U16.8)
-3V_PFCLC: P3 Bias POWER SUPPLY (C107.2 C109.2 U13.5), P4 PFC Gate Driver (C150.2 C152.2 U20.8)
AGND: P1 Input and EMI filter (6 pins), P2 PFC (24 pins), P3 Bias POWER SUPPLY (14 pins), P4 PFC Gate Driver (42 pins), P5 PFC sampling (33 pins)
ClampHA: P2 PFC (5 pins), P4 PFC Gate Driver (U17.7)
ClampHB: P2 PFC (5 pins), P4 PFC Gate Driver (U15.7)
ClampHC: P2 PFC (5 pins), P4 PFC Gate Driver (U19.7)
ClampLA: P2 PFC (5 pins), P4 PFC Gate Driver (U18.7)
ClampLB: P2 PFC (5 pins), P4 PFC Gate Driver (U16.7)
ClampLC: P2 PFC (5 pins), P4 PFC Gate Driver (U20.7)
GGND: P1 Input and EMI filter (18 pins), P3 Bias POWER SUPPLY (31 pins)
PFC_G_HA: P2 PFC (C7.2 Q7.3 R74.1), P3 Bias POWER SUPPLY (6 pins), P4 PFC Gate Driver (C130.2 C131.1)
PFC_G_HB: P2 PFC (C8.2 Q8.3 R75.1), P3 Bias POWER SUPPLY (6 pins), P4 PFC Gate Driver (C116.2 C117.1)
PFC_G_HC: P2 PFC (C9.2 Q9.3 R76.1), P3 Bias POWER SUPPLY (6 pins), P4 PFC Gate Driver (C144.2 C145.1)
PFC_G_LA: P2 PFC (C36.2 Q11.3 R91.1), P3 Bias POWER SUPPLY (6 pins), P4 PFC Gate Driver (C137.2 C138.1)
PFC_G_LB: P2 PFC (C34.2 Q10.3 R87.1), P3 Bias POWER SUPPLY (6 pins), P4 PFC Gate Driver (C123.2 C124.1)
PFC_G_LC: P2 PFC (C35.2 Q12.3 R88.1), P3 Bias POWER SUPPLY (6 pins), P4 PFC Gate Driver (C151.2 C152.1)
PFCDRVHA: P2 PFC (D13.2 R69.1), P4 PFC Gate Driver (U17.6)
PFCDRVHB: P2 PFC (D16.2 R70.1), P4 PFC Gate Driver (U15.6)
PFCDRVHC: P2 PFC (D17.2 R71.1), P4 PFC Gate Driver (U19.6)
PFCDRVLA: P2 PFC (D14.2 R86.1), P4 PFC Gate Driver (U18.6)
PFCDRVLB: P2 PFC (D15.2 R82.1), P4 PFC Gate Driver (U16.6)
PFCDRVLC: P2 PFC (D18.2 R85.1), P4 PFC Gate Driver (U20.6)
PGND: P2 PFC (27 pins), P3 Bias POWER SUPPLY (8 pins)
PWM1A: P3 Bias POWER SUPPLY (J1.1), P4 PFC Gate Driver (R126.1)
PWM1B: P3 Bias POWER SUPPLY (J1.3), P4 PFC Gate Driver (R130.1)
PWM1C: P3 Bias POWER SUPPLY (J1.5), P4 PFC Gate Driver (R118.1)
PWM1D: P3 Bias POWER SUPPLY (J1.7), P4 PFC Gate Driver (R122.1)
PWM1E: P3 Bias POWER SUPPLY (J1.9), P4 PFC Gate Driver (R134.1)
PWM1F: P3 Bias POWER SUPPLY (J1.11), P4 PFC Gate Driver (R138.1)
RLYCTRL1: P1 Input and EMI filter (R58.2), P3 Bias POWER SUPPLY (J1.2)
RLYCTRL2: P1 Input and EMI filter (R67.2), P3 Bias POWER SUPPLY (J1.4)
VO1+: P2 PFC (R93.1), P3 Bias POWER SUPPLY (J2.1)
VO2+: P2 PFC (R94.1), P3 Bias POWER SUPPLY (J2.3)
VP3.3D: P2 PFC (R95.1 R98.1 R103.1 R106.1), P3 Bias POWER SUPPLY (J1.6), P5 PFC sampling (6 pins)
VP+5V: P1 Input and EMI filter (C3.1 C6.1 R52.2 R65.2), P3 Bias POWER SUPPLY (5 pins), P4 PFC Gate Driver (12 pins), P5 PFC sampling (9 pins)
VP+15V_PFCHA: P3 Bias POWER SUPPLY (C59.1 C60.1 C61.1 U10.7), P4 PFC Gate Driver (R128.2)
VP+15V_PFCHB: P3 Bias POWER SUPPLY (C77.1 C80.1 C81.1 U12.7), P4 PFC Gate Driver (R120.2)
VP+15V_PFCHC: P3 Bias POWER SUPPLY (C95.1 C98.1 C99.1 U14.7), P4 PFC Gate Driver (R135.2)
VP+15V_PFCLA: P3 Bias POWER SUPPLY (C56.1 C57.1 C58.1 U9.7), P4 PFC Gate Driver (R132.2)
VP+15V_PFCLB: P3 Bias POWER SUPPLY (C74.1 C75.1 C76.1 U11.7), P4 PFC Gate Driver (R124.2)
VP+15V_PFCLC: P3 Bias POWER SUPPLY (C92.1 C93.1 C94.1 U13.7), P4 PFC Gate Driver (R140.2)
NetC214_2: P3 Bias POWER SUPPLY (J2.2), P5 PFC sampling (C214.2 R154.2 U24.1)
NetC217_2: P3 Bias POWER SUPPLY (J2.4), P5 PFC sampling (C217.2 R164.2 U27.1)
NetC219_2: P3 Bias POWER SUPPLY (J2.6), P5 PFC sampling (C219.2 R179.2 U31.1)
NetCL2_A1_2: P1 Input and EMI filter (7 pins), P5 PFC sampling (R265.1)
NetCL2_A1_4: P1 Input and EMI filter (7 pins), P5 PFC sampling (R264.1)
NetCL2_A1_6: P1 Input and EMI filter (7 pins), P5 PFC sampling (R266.1)
NetJ1_8: P2 PFC (R100.2 U4.13), P3 Bias POWER SUPPLY (J1.8)
NetJ1_10: P2 PFC (R105.2 U5.13), P3 Bias POWER SUPPLY (J1.10)
NetJ1_12: P2 PFC (R108.2 U6.13), P3 Bias POWER SUPPLY (J1.12)
NetJ1_14: P2 PFC (U3.12), P3 Bias POWER SUPPLY (J1.14)
NetJ1_15: P2 PFC (U4.12), P3 Bias POWER SUPPLY (J1.15)
NetJ1_16: P2 PFC (R97.2 U3.13), P3 Bias POWER SUPPLY (J1.16)
NetJ1_17: P2 PFC (U5.12), P3 Bias POWER SUPPLY (J1.17)
NetJ1_19: P2 PFC (U6.12), P3 Bias POWER SUPPLY (J1.19)
NetJ4_5: P1 Input and EMI filter (R36.1 R57.1 R191.1), P3 Bias POWER SUPPLY (J4.5)
NetR29_2: P1 Input and EMI filter (R29.2), P5 PFC sampling (R146.1)
NetR38_2: P1 Input and EMI filter (R38.2), P5 PFC sampling (R163.1)
NetR46_2: P1 Input and EMI filter (R46.2), P5 PFC sampling (R181.1)
NetRLY1_4: P1 Input and EMI filter (RLY1.4 RV2.1), P2 PFC (U4.1 U4.2 U4.3 U4.4)
NetRLY2_4: P1 Input and EMI filter (RLY2.4 RV4.1), P2 PFC (U5.1 U5.2 U5.3 U5.4)
NetRLY3_4: P1 Input and EMI filter (RLY3.4 RV5.1), P2 PFC (U6.1 U6.2 U6.3 U6.4)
